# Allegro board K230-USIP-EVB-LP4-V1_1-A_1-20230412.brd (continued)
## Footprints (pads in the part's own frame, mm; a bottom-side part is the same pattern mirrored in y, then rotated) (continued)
DSW3-087044-047-H
  oval 1.778x2.54 hole 1.016x1.778: (-4.15,0) (4.15,0)
  rect 1.524x1.524 hole 1.016: 1(-2,0)
  round 1.524 hole 1.016: 2(0,0) 3(2,0)
DSW4-KH-6X6X7H-ZJ
  round 1.778 hole 1.143: 1(-2.25,-1.25) 2(2.25,-1.25)
  round 1.905 hole 1.397: 3(-3.5,1.25) 4(3.5,1.25)
F1206
  rect 1.397x1.651 smd: 1(-1.397,0) 2(1.397,0)
FB0402
  rect 0.635x0.508 smd: 1(-0.508,0) 2(0.508,0)
FB0603
  rect 0.762x0.813 smd: 1(-0.762,0) 2(0.762,0)
FB1206
  rect 1.397x1.651 smd: 1(-1.397,0) 2(1.397,0)
FPC30-005-0520-75
  rect 0.305x1.016 smd: 1(7.248,0) 2(6.748,0) 3(6.248,0) 4(5.749,0) 5(5.249,0) 6(4.749,0) 7(4.249,0) 8(3.749,0) 9(3.249,0) 10(2.749,0) 11(2.249,0) 12(1.75,0) 13(1.25,0) 14(0.75,0) 15(0.25,0) 16(-0.25,0) 17(-0.75,0) 18(-1.25,0) 19(-1.75,0) 20(-2.249,0) 21(-2.749,0) 22(-3.249,0) 23(-3.749,0) 24(-4.249,0) 25(-4.749,0) 26(-5.249,0) 27(-5.749,0) 28(-6.248,0) 29(-6.748,0) 30(-7.248,0)
  rect 2.032x1.321 smd: 31(-9.548,-2.7) 32(9.548,-2.7)
HEAD2-100
  rect 1.524x1.524 hole 1.016: 1(0,0)
  round 1.524 hole 1.016: 2(2.54,0)
HEAD2X8-100
  rect 1.524x1.524 hole 1.016: 1(0,0)
  round 1.524 hole 1.016: 2(0,2.54) 3(2.54,0) 4(2.54,2.54) 5(5.08,0) 6(5.08,2.54) 7(7.62,0) 8(7.62,2.54) 9(10.16,0) 10(10.16,2.54) 11(12.7,0) 12(12.7,2.54) 13(15.24,0) 14(15.24,2.54) 15(17.78,0) 16(17.78,2.54)
HEAD3-100
  rect 1.524x1.524 hole 1.016: 1(0,0)
  round 1.524 hole 1.016: 2(2.54,0) 3(5.08,0)
HEAD6-100
  rect 1.524x1.524 hole 1.016: 1(0,0)
  round 1.524 hole 1.016: 2(2.54,0) 3(5.08,0) 4(7.62,0) 5(10.16,0) 6(12.7,0)
HEAD10-100
  rect 1.524x1.524 hole 1.016: 1(-7.62,0)
  round 1.524 hole 1.016: 2(-5.08,0) 3(-2.54,0) 4(0,0) 5(2.54,0) 6(5.08,0) 7(7.62,0) 8(10.16,0) 9(12.7,0) 10(15.24,0)
HOLE-M3
  round 5.969 hole 3.175: 1(0,0)
LED0603
  rect 0.762x0.813 smd: 1(-0.762,0) 2(0.762,0)
MIC4-028019-010
  rect 0.635x0.635 smd: 1(0.508,0.965) 2(0.508,-0.965) 3(-0.508,-0.965) 4(-0.508,0.965)
PL02_502-01
  rect 0.762x2.413 smd: 1(-1.016,0) 2(1.016,0)
PL0303-017A
  rect 1.397x2.413 smd: 1(-1.397,0) 2(1.397,0)
PL0505-030
  rect 1.524x2.032 smd: 1(-2.112,0) 2(2.112,0)
QFN8-050-0202-008-N
  rect 0.305x0.457 smd: 1(-0.75,-0.979) 2(-0.25,-0.979) 3(0.25,-0.979) 4(0.75,-0.979) 5(0.75,0.979) 6(0.25,0.979) 7(-0.25,0.979) 8(-0.75,0.979)
  rect 1.524x0.889 smd: 9(0,0)
QFN12-040-018018-006
  rect 0.762x0.203 smd: 1(-0.9,0.2) 2(-0.9,-0.2) 7(0.9,-0.2) 8(0.9,0.2)
  rect 0.203x0.762 smd: 3(-0.6,-0.9) 4(-0.2,-0.9) 5(0.2,-0.9) 6(0.6,-0.9) 9(0.6,0.9) 10(0.2,0.9) 11(-0.2,0.9) 12(-0.6,0.9)
QFN20-050-0404-008-N
  oval 0.254x0.838 smd: 1(-1,-2.011) 2(-0.5,-2.011) 3(0,-2.011) 4(0.5,-2.011) 5(1,-2.011) 11(1,2.011) 12(0.5,2.011) 13(0,2.011) 14(-0.5,2.011) 15(-1,2.011)
  oval 0.838x0.254 smd: 6(2.011,-1) 7(2.011,-0.5) 8(2.011,0) 9(2.011,0.5) 10(2.011,1) 16(-2.011,1) 17(-2.011,0.5) 18(-2.011,0) 19(-2.011,-0.5) 20(-2.011,-1)
  rect 2.54x2.54 smd: 21(0,0)
QFN24-050-0404-010-N
  oval 0.254x0.838 smd: 1(-1.25,-2.094) 2(-0.75,-2.094) 3(-0.25,-2.094) 4(0.25,-2.094) 5(0.75,-2.094) 6(1.25,-2.094) 13(1.25,2.094) 14(0.75,2.094) 15(0.25,2.094) 16(-0.25,2.094) 17(-0.75,2.094) 18(-1.25,2.094)
  oval 0.838x0.254 smd: 7(2.094,-1.25) 8(2.094,-0.75) 9(2.094,-0.25) 10(2.094,0.25) 11(2.094,0.75) 12(2.094,1.25) 19(-2.094,1.25) 20(-2.094,0.75) 21(-2.094,0.25) 22(-2.094,-0.25) 23(-2.094,-0.75) 24(-2.094,-1.25)
  rect 2.54x2.54 smd: 25(0,0)
QFN64-050-0909-010-N
  oval 1.016x0.254 smd: 1(-4.55,3.75) 2(-4.55,3.25) 3(-4.55,2.75) 4(-4.55,2.25) 5(-4.55,1.75) 6(-4.55,1.25) 7(-4.55,0.75) 8(-4.55,0.25) 9(-4.55,-0.25) 10(-4.55,-0.75) 11(-4.55,-1.25) 12(-4.55,-1.75) 13(-4.55,-2.25) 14(-4.55,-2.75) 15(-4.55,-3.25) 16(-4.55,-3.75) 33(4.55,-3.75) 34(4.55,-3.25) 35(4.55,-2.75) 36(4.55,-2.25) 37(4.55,-1.75) 38(4.55,-1.25) 39(4.55,-0.75) 40(4.55,-0.25) 41(4.55,0.25) 42(4.55,0.75) 43(4.55,1.25) 44(4.55,1.75) 45(4.55,2.25) 46(4.55,2.75) 47(4.55,3.25) 48(4.55,3.75)
  oval 0.254x1.016 smd: 17(-3.75,-4.55) 18(-3.25,-4.55) 19(-2.75,-4.55) 20(-2.25,-4.55) 21(-1.75,-4.55) 22(-1.25,-4.55) 23(-0.75,-4.55) 24(-0.25,-4.55) 25(0.25,-4.55) 26(0.75,-4.55) 27(1.25,-4.55) 28(1.75,-4.55) 29(2.25,-4.55) 30(2.75,-4.55) 31(3.25,-4.55) 32(3.75,-4.55) 49(3.75,4.55) 50(3.25,4.55) 51(2.75,4.55) 52(2.25,4.55) 53(1.75,4.55) 54(1.25,4.55) 55(0.75,4.55) 56(0.25,4.55) 57(-0.25,4.55) 58(-0.75,4.55) 59(-1.25,4.55) 60(-1.75,4.55) 61(-2.25,4.55) 62(-2.75,4.55) 63(-3.25,4.55) 64(-3.75,4.55)
  rect 4.699x4.699 smd: 65(0,0)
R0402
  rect 0.635x0.508 smd: 1(-0.508,0) 2(0.508,0)
R0603
  rect 0.762x0.813 smd: 1(-0.762,0) 2(0.762,0)
R0805
  rect 1.016x1.397 smd: 1(-0.889,0) 2(0.889,0)
SOD523-2-28
  rect 0.508x0.406 smd: 1(-0.889,0) 2(0.889,0)
SOD523-2-28-H
  rect 0.508x0.406 smd: 1(-0.66,0) 2(0.66,0)
SOP16-75
  rect 2.032x1.016 smd: 1(-8.89,6.668) 2(-8.89,4.763) 3(-8.89,2.857) 4(-8.89,0.953) 5(-8.89,-0.953) 6(-8.89,-2.857) 7(-8.89,-4.763) 8(-8.89,-6.668) 9(8.89,-6.668) 10(8.89,-4.763) 11(8.89,-2.857) 12(8.89,-0.953) 13(8.89,0.953) 14(8.89,2.857) 15(8.89,4.763) 16(8.89,6.668)
SOT23-3-43
  rect 0.762x0.889 smd: 1(-0.95,-1.143) 2(0.95,-1.143) 3(0,1.143)
SOT23-5-36
  rect 0.635x1.016 smd: 1(-0.953,-1.295) 2(0,-1.295) 3(0.953,-1.295) 4(0.953,1.295) 5(-0.953,1.295)
SOT23-5-57
  rect 0.635x1.016 smd: 1(-0.953,-1.245) 2(0,-1.245) 3(0.953,-1.245) 4(0.953,1.245) 5(-0.953,1.245)
SOT143-4-48
  rect 1.016x1.143 smd: 1(-0.747,-1.143)
  rect 0.635x1.143 smd: 2(0.953,-1.143) 3(0.953,1.143) 4(-0.953,1.143)
SW2-061036-025
  rect 2.032x1.016 smd: 1(3.016,0) 2(-3.016,0)
SW4-100-060050-035
  rect 1.016x2.159 smd: 1(-1.27,-4.386) 2(1.27,-4.386) 3(-1.27,4.386) 4(1.27,4.386)
TC1206
  rect 1.397x1.651 smd: 1(-1.397,0) 2(1.397,0)
TP28
  round 0.711 smd: 1(0,0)
TP40
  round 1.016 smd: 1(0,0)
TYPE-C-USB16-20-126-H-SMD-B
  round 0.711 hole 0.711 unplated: (-2.89,2.6) (2.89,2.6)
  rect 0.305x1.448 smd: A1(-3.375,3.974) A4(-2.6,3.974) A5(-1.25,3.974) A6(-0.25,3.974) A7(0.25,3.974) A8(1.25,3.974) A9(2.6,3.974) A12(3.375,3.974) B1(3.075,3.974) B4(2.3,3.974) B5(1.75,3.974) B6(0.75,3.974) B7(-0.75,3.974) B8(-1.75,3.974) B9(-2.3,3.974) B12(-3.075,3.974)
  oval 1.143x2.159 hole 0.762x1.778: P1(-4.32,3.13) P2(4.32,3.13)
  oval 1.143x1.651 hole 0.762x1.27: P3(-4.32,-1.05) P4(4.32,-1.05)
unnamed
  round 1.016 smd: 1(0,0)
X2-3215-008
  rect 1.016x1.778 smd: 1(-1.257,0) 2(1.257,0)
X4-2520-010
  rect 1.016x0.889 smd: 1(-0.914,-0.762) 2(0.914,-0.762) 3(0.914,0.762) 4(-0.914,0.762)
X4-3225-007
  rect 1.27x1.143 smd: 1(-1.1,-0.8) 2(1.1,-0.8) 3(1.1,0.8) 4(-1.1,0.8)

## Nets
AVDD_1V8: C14.1 C15.1 C151.1 C361.1 C362.1 FB27.2 R35.1 R80.1 R131.2 R132.1 TP11.1(TP) U1.F7(AVDD1P8_CODEC) U1.F8(AVDD1P8_ADC)
AVDD_PLL_0V8: C32.1 C365.1 C366.1 FB29.2 TP7.1(TP) U1.G11(AVDD0P8_PLL)
GND: C1.2 C2.2 C3.2 C4.2 C5.2 C6.2 C7.2 C8.2 C9.2 C10.2 C11.2 C12.2 C13.1 C14.2 C15.2 C16.1 C17.2 C18.2 C19.2 C20.1 C21.2 C22.2 C23.1 C24.2 C25.2 C26.2 C27.2 C28.2 C29.2 C30.2 C31.2 C32.2 C33.2 C34.2 C35.2 C36.2 C37.2 C38.2 C39.2 C40.2 C41.2 C42.2 C43.2 C44.2 C45.2 C46.2 C47.2 C48.2 C49.2 C50.2 C51.2 C52.2 C53.2 C54.2 C55.2 C56.2 C57.2 C58.2 C59.2 C60.2 C61.2 C63.2 C64.2 C65.2 C66.2 C67.2 C68.2 C69.2 C70.2 C71.2 C72.2 C73.2 C74.2 C75.2 C76.2 C77.2 C78.2 C79.2 C80.2 C81.2 C82.2 C83.2 C84.2 C85.2 C86.2 C87.2 C88.2 C89.2 C90.2 C91.2 C92.2 C93.2 C94.2 C95.2 C96.2 C97.2 C98.2 C99.2 C100.2 C101.2 C102.2 C103.2 C104.2 C105.2 C106.2 C107.2 C108.2 C109.2 C110.2 C111.2 C112.2 C113.2 C114.2 C115.2 C116.2 C117.2 C118.2 C119.2 C120.2 C121.2 C122.2 C123.2 C127.2 C128.1 C129.2 C139.2 C145.2 C149.2 C150.2 C151.2 C152.2 C153.2 C154.2 C155.2 C156.2 C158.1 C160.1 C162.2 C199.1 C200.1 C201.2 C202.1 C203.1 C204.2 C205.2 C206.1 C207.2 C208.1 C216.1 C217.1 C218.1 C219.1 C220.1 C221.1 C222.1 C223.2 C224.2 C225.2 C226.2 C227.1 C242.1 C244.1 C247.2 C248.2 C249.2 C250.2 C251.2 C252.2 C253.2 C254.2 C256.2 C257.2 C258.2 C259.2 C260.2 C261.1 C262.2 C263.2 C264.2 C265.2 C266.2 C268.2 C269.2 C272.2 C273.2 C274.2 C275.2 C276.2 C277.2 C278.2 C279.2 C280.2 C281.2 C282.2 C283.2 C284.2 C285.2 C286.2 C287.2 C288.2 C289.2 C290.2 C291.2 C292.2 C293.2 C294.2 C295.2 C296.2 C297.2 C298.2 C299.2 C300.2 C301.2 C302.2 C303.2 C304.2 C305.2 C306.2 C307.2 C308.2 C310.1 C312.1 C313.2 C314.2 C315.2 C316.1 C317.2 C318.2 C319.2 C321.2 C322.2 C324.2 C325.2 C326.2 C327.2 C329.2 C330.2 C331.2 C333.2 C334.2 C335.2 C336.2 C337.2 C338.2 C339.2 C340.2 C341.2 C342.2 C343.2 C344.2 C345.2 C346.2 C347.2 C348.2 C349.2 C350.2 C351.2 C352.2 C353.2 C354.2 C357.2 C358.2 C359.2 C360.2 C361.2 C362.2 C365.2 C366.2 C367.1 C368.2 C369.1 C370.2 C371.2 C372.2 C373.2 C374.2 C375.2 C376.2 C377.1 C378.2 C379.2 C380.2 C381.1 C383.2 C394.2 C395.2 C396.2 C397.2 C398.2 C399.2 C400.2 C401.2 C402.2 C403.1 C404.1 D1.1(ANODE) J1.6 J1.12 J2.A1(GND0) J2.A12(GND1) J2.B1(GND3) J2.B12(GND2) J2.P1 J2.P2 J2.P3 J2.P4 J3.5 J3.6 J3.11 J3.12 J3.17 J3.18 J3.23 J3.24 J3.28 J3.29 J3.33 J3.37 J3.54 J3.55 J4.1 J4.2 J4.7 J4.12 J4.15 J4.18 J4.21 J4.24 J4.27 J4.30 J4.31 J4.32 J5.5 J5.11 J5.12 J6.A1(GND0) J6.A12(GND1) J6.B1(GND3) J6.B12(GND2) J6.P1 J6.P2 J6.P3 J6.P4 J7.2 J8.10 J8.14 J9.2 J9.15 J11.A1(GND0) J11.A12(GND1) J11.B1(GND3) J11.B12(GND2) J11.P1 J11.P2 J11.P3 J11.P4 J12.2 J12.9 J12.10 J13.A1(GND0) J13.A12(GND1) J13.B1(GND3) J13.B12(GND2) J13.P1 J13.P2 J13.P3 J13.P4 J14.1 J14.2 J17.2 K1.3 K1.4 K2.1 K4.3 LED1.2(ANODE) M1.1 M2.1 M3.1 M4.1 M5.1 M6.1 Q2.2(SOURCE) R7.2 R9.2 R13.2 R14.2 R40.1 R41.2 R42.2 R44.2 R45.1 R46.2 R56.1 R58.2 R61.2 R72.2 R73.2 R74.2 R130.1 R133.2 R134.2 R137.1 R178.2 R195.2 R202.1 R252.1 R266.1 R268.1 R271.2 R276.1 R278.1 R279.2 R282.1 R286.2 R290.2 R296.2 TP15.1(TP) TP16.1(TP) TP17.1(TP) TP18.1(TP) TP19.1(TP) TP20.1(TP) TP21.1(TP) TP22.1(TP) TVS1.2(A2) TVS2.2(A2) TVS3.2(A2) TVS4.2(A2) TVS5.2(A2) TVS6.2(A2) TVS7.2(A2) TVS8.2(A2) TVS9.2(A2) TVS10.2(A2) TVS11.2(A2) TVS12.2(A2) TVS13.2(A2) TVS14.2(A2) U1.A13(VSS91) U1.A16(VSS90) U1.A19(VSS92) U1.B13(VSS93) U1.B20(VSS94) U1.C13(VSS95) U1.D9(VSS96) U1.D10(VSS99) U1.D11(VSS97) U1.D13(VSS98) U1.D15(VSS100) U1.E4(VSS75) U1.E6(VSS72) U1.E7(VSS73) U1.E8(VSS74) U1.E12(VSS78) U1.E13(VSS79) U1.E14(VSS80) U1.E15(VSS81) U1.E16(VSS82) U1.E19(VSS77) U1.F4(VSS53) U1.F6(VSS55) U1.F10(VSS76) U1.F11(AVSS3) U1.F16(VSS54) U1.G6(VSS89) U1.G7(AVSS2) U1.G8(AVSS1) U1.G13(VSS49) U1.G14(VSS50) U1.G15(VSS51) U1.G16(VSS52) U1.H7(VSS88) U1.H11(VSS83) U1.H13(VSS85) U1.H15(VSS86) U1.H16(VSS87) U1.H20(VSS84) U1.J7(VSS3) U1.J11(VSS1) U1.J13(VSS0) U1.J15(VSS2) U1.K3(VSS4) U1.K6(VSS7) U1.K8(VSS9) U1.K10(VSS10) U1.K12(VSS8) U1.K14(VSS6) U1.K16(VSS5) U1.K18(VSS56) U1.L7(VSS11) U1.L8(VSS12) U1.L10(VSS14) U1.L12(VSS16) U1.L15(VSS15) U1.L19(VSS13) U1.M6(VSS17) U1.M8(VSS19) U1.M10(VSS20) U1.M12(VSS18) U1.M15(VSS21) U1.M16(VSS22) U1.N3(VSS26) U1.N5(VSS24) U1.N8(VSS27) U1.N10(VSS23) U1.N12(VSS25) U1.N15(VSS28) U1.N16(VSS29) U1.P6(VSS30) U1.P7(VSS31) U1.P8(VSS32) U1.P10(VSS34) U1.P12(VSS33) U1.P14(VSS43) U1.P15(VSS44) U1.P20(VSS40) U1.R3(VSS36) U1.R6(VSS38) U1.R7(VSS39) U1.R10(VSS41) U1.R12(VSS42) U1.R14(VSS35) U1.R16(VSS37) U1.T3(VSS48) U1.T7(VSS45) U1.T8(VSS46) U1.T9(VSS47) U1.T15(VSS60) U1.U3(VSS59) U1.U8(VSS58) U1.U19(VSS57) U1.V3(VSS61) U1.V4(VSS62) U1.V5(VSS63) U1.V6(VSS64) U1.V7(VSS65) U1.V8(VSS66) U1.W1(VSS67) U1.W16(VSS68) U1.W20(VSS71) U1.Y13(VSS69) U1.Y19(VSS70) U3.2(GND) U4.6(VSS) U4.10(GND1) U4.11(GND2) U4.12(GND3) U4.13(GND4) U5.A3(VSS1) U5.A10(VSS2) U5.AB3(VSS55) U5.AB5(VSS56) U5.AB8(VSS57) U5.AB10(VSS58) U5.C1(VSS3) U5.C5(VSS4) U5.C8(VSS5) U5.C12(VSS6) U5.D2(VSS7) U5.D4(VSS8) U5.D9(VSS9) U5.D11(VSS10) U5.E1(VSS11) U5.E5(VSS12) U5.E8(VSS13) U5.E12(VSS14) U5.G1(VSS15) U5.G3(VSS16) U5.G5(VSS17) U5.G8(VSS18) U5.G10(VSS19) U5.G12(VSS20) U5.J1(VSS21) U5.J3(VSS22) U5.J10(VSS23) U5.J12(VSS24) U5.K2(VSS25) U5.K4(VSS26) U5.K9(VSS27) U5.K11(VSS28) U5.N2(VSS29) U5.N4(VSS30) U5.N9(VSS31) U5.N11(VSS32) U5.P1(VSS33) U5.P3(VSS34) U5.P10(VSS35) U5.P12(VSS36) U5.T1(VSS37) U5.T3(VSS38) U5.T5(VSS39) U5.T8(VSS40) U5.T10(VSS41) U5.T12(VSS42) U5.V1(VSS43) U5.V5(VSS44) U5.V8(VSS45) U5.V12(VSS46) U5.W2(VSS47) U5.W4(VSS48) U5.W9(VSS49) U5.W11(VSS50) U5.Y1(VSS51) U5.Y5(VSS52) U5.Y8(VSS53) U5.Y12(VSS54) U6.2(GND) U7.A3(VSS1) U7.A10(VSS2) U7.AB3(VSS55) U7.AB5(VSS56) U7.AB8(VSS57) U7.AB10(VSS58) U7.C1(VSS3) U7.C5(VSS4) U7.C8(VSS5) U7.C12(VSS6) U7.D2(VSS7) U7.D4(VSS8) U7.D9(VSS9) U7.D11(VSS10) U7.E1(VSS11) U7.E5(VSS12) U7.E8(VSS13) U7.E12(VSS14) U7.G1(VSS15) U7.G3(VSS16) U7.G5(VSS17) U7.G8(VSS18) U7.G10(VSS19) U7.G12(VSS20) U7.J1(VSS21) U7.J3(VSS22) U7.J10(VSS23) U7.J12(VSS24) U7.K2(VSS25) U7.K4(VSS26) U7.K9(VSS27) U7.K11(VSS28) U7.N2(VSS29) U7.N4(VSS30) U7.N9(VSS31) U7.N11(VSS32) U7.P1(VSS33) U7.P3(VSS34) U7.P10(VSS35) U7.P12(VSS36) U7.T1(VSS37) U7.T3(VSS38) U7.T5(VSS39) U7.T8(VSS40) U7.T10(VSS41) U7.T12(VSS42) U7.V1(VSS43) U7.V5(VSS44) U7.V8(VSS45) U7.V12(VSS46) U7.W2(VSS47) U7.W4(VSS48) U7.W9(VSS49) U7.W11(VSS50) U7.Y1(VSS51) U7.Y5(VSS52) U7.Y8(VSS53) U7.Y12(VSS54) U9.3(GND) U9.7(POWERPAD) U16.4(PGND1) U16.12(PGND2) U16.18(AGND) U16.21(EXP) U22.1(GND) U23.1(GND) U24.1(GND) U25.7(GND) U26.1(GND#1) U26.5(GND#5) U26.10(AGND) U26.11(GND#11) U26.13(TEST) U26.15(GND#15) U26.25(GND#25) U26.35(GND#35) U26.47(GND#47) U26.51(GND#51) U26.65(PAD) U29.2(GND1) U29.3(GND2) U30.A6(VSS#A6) U30.C4(VSSQ#C4) U30.E7(VSS#E7) U30.G5(VSS#G5) U30.H10(VSS#H10) U30.J5(VSS#J5) U30.K8(VSS#K8) U30.N2(VSSQ#N2) U30.N5(VSSQ#N5) U30.P4(VSSQ#P4) U30.P6(VSSQ#P6) U31.1(GND) U32.1(GND) U33.1(GND) U34.7(GND) U35.4(GND2) U35.25(GND4) U36.7(GND) U37.3(GND) U37.7(POWERPAD) U38.4(PGND1) U38.8(SGND) U38.9(PGND2) Y3.2(GND#2) Y3.4(GND#4) Y5.2(GND#2) Y5.4(GND#4)
GND3: R289.1 R290.1 U35.1(GND3)
VBUS: F1.1 J2.A4(VBUS0) J2.A9(VBUS1) J2.B4(VBUS3) J2.B9(VBUS2)
VBUS_IN: C9.1 C12.1 C247.1 C248.1 C249.1 C250.1 D1.2(CATHODE) F1.2 Q5.2(SOURCE) R303.1
VDD0V8_KPU_EN: C394.1 R301.1 U38.7(EN)
VDD_0V8: C317.1 C318.1 C319.1 C320.1 FB29.1 FB31.1 FB32.1 L5.2 R267.2 R309.1 R310.1
VDD_1V1: C325.1 C326.1 C327.1 C328.1 L7.2 R275.1 R307.1
VDD_1V8: C23.2 C26.1 C28.1 C29.1 C31.1 C78.1 C79.1 C80.1 C206.2 C207.1 C242.2 C256.1 C257.1 C258.1 C259.1 C315.1 C321.1 C322.1 C323.1 C324.1 FB5.2 FB19.1 FB26.1 FB27.1 J5.7 J5.9 J8.12 J9.1 J12.1 L11.2 R18.2 R20.2 R48.2 R49.2 R59.2 R129.1 R146.1 R197.1 R198.1 R199.1 R200.1 R206.1 R207.1 R209.1 R234.1 R235.1 R236.1 R237.1 R238.1 R239.1 R240.1 R241.1 R269.2 R280.2 R311.1 R312.1 TP9.1(TP) U1.E11(VDD1P8#E11) U1.F13(VDD1P8#F13) U1.H6(VDDIO3P3_3) U1.R11(VDDIO3P3_2) U1.R13(VDDIO3P3_0) U1.R15(VDDIO3P3_5) U25.2(VCCA) U30.C6(VCCQ#C6) U30.M4(VCCQ#M4) U30.N4(VCCQ#N4) U30.P3(VCCQ#P3) U30.P5(VCCQ#P5) U34.2(VCCA)
VDD_3V3: C18.1 C19.1 C22.1 C30.1 C81.1 C82.1 C83.1 C139.1 C145.1 C208.2 C227.2 C244.2 C260.1 C316.2 C367.2 C399.1 C403.2 FB4.2 J3.57 J3.59 J4.5 J4.6 J5.13 J5.15 J8.16 J9.16 R11.2 R19.1 R76.1 R162.1 R188.1 R189.1 R190.1 R191.1 R193.1 R194.1 R242.1 R243.1 R245.2 R283.2 R284.2 R288.1 R305.2 R306.2 R308.2 TP10.1(TP) U1.E10(VDD3P3_SD) U1.M7(VDDIO3P3_4) U4.4(VDD) U25.1(VCCB) U30.E6(VCC#E6) U30.F5(VCC#F5) U30.J10(VCC#J10) U30.K9(VCC#K9) U34.1(VCCB) U36.2(VCCA)
VDD_5V: C2.1 C127.1 C337.1 C338.1 C339.1 C340.1 C379.1 C381.2 C383.1 C397.1 C398.1 C401.1 Q1.2(SOURCE) Q5.3(DRAIN) R23.2 R75.1 R143.1 R265.2 R272.2 R273.2 R274.2 R277.1 R289.2 R293.1 R301.2 R302.1 R304.1 TP23.1(TP) U9.6(IN) U35.8(VIN2) U35.11(VIN1) U35.20(VIN4) U35.23(VIN3) U38.3(IN) U39.1(VIN) U39.2(GND)
VDD_5V_O: C16.2 C20.2 J3.56 J3.58 J3.60 J4.3 J4.4 J5.14 J5.16 Q1.3(DRAIN) R39.2 R43.2 R75.2 R88.2 TP24.1(TP) U3.5(IN) U6.5(IN)
VDD_CORE_0V8: C33.1 C34.1 C35.1 C36.1 C37.1 C38.1 C39.1 C40.1 C41.1 C42.1 C43.1 C44.1 C45.1 C46.1 C47.1 C48.1 C57.1 C58.1 C59.1 C60.1 C61.1 C251.1 C253.1 C351.1 C352.1 C371.1 C372.1 FB31.2 TP5.1(TP) TP6.1(TP) U1.F12(VDD0P8_CORE#F12) U1.G9(VDD0P8_CORE#G9) U1.G10(VDD0P8_CORE#G10) U1.G12(VDD0P8_CPU#G12) U1.H12(VDD0P8_CPU#H12) U1.J12(VDD0P8_CPU#J12) U1.K9(VDD0P8_CORE#K9) U1.K11(VDD0P8_CORE#K11) U1.L9(VDD0P8_CORE#L9) U1.L11(VDD0P8_CORE#L11) U1.M9(VDD0P8_CORE#M9) U1.M11(VDD0P8_CORE#M11) U1.N9(VDD0P8_CORE#N9) U1.N11(VDD0P8_CORE#N11) U1.P9(VDD0P8_CORE#P9) U1.P11(VDD0P8_CORE#P11) U1.P13(VDD0P8_CORE#P13)
VDD_KPU_0V8: C49.1 C50.1 C51.1 C52.1 C53.1 C54.1 C55.1 C56.1 C252.1 C254.1 C353.1 C354.1 C373.1 C374.1 C375.1 C376.1 C400.1 FB32.2 FB34.2 FB38.2 TP8.1(TP) U1.H8(VDD0P8_KPU#H8) U1.H9(VDD0P8_KPU#H9) U1.H10(VDD0P8_KPU#H10) U1.J8(VDD0P8_KPU#J8) U1.J9(VDD0P8_KPU#J9) U1.J10(VDD0P8_KPU#J10)
VDD_PA: C7.1 C303.1 C304.1 C308.1 R11.1 R88.1 U16.3(PVDD1) U16.9(AVDD) U16.13(PVDD2)
3D_CTRL_IN: J3.49 R83.1
3D_CTRL_OUT1: J3.47 R85.1
3D_CTRL_OUT2: J3.46 R87.1
ACRC: C313.1 R134.1 U16.1(ACRC)
ADC_0: J15.1 R25.1 R51.1
ADC_1: J15.2 R26.1 R52.1
ADC_2: J3.52 J15.3 R27.1
ADC_3: J15.4 R28.1
ADC_4: J15.5 R29.1
ADC_5: J15.6 R30.1 R221.1
BOOT0: R18.1 SW1.1(A1) TVS4.1(A1) U1.C8(GPIO0)
BOOT1: R20.1 SW1.2(A2) TVS5.1(A1) U1.C9(GPIO1)
CA_A0: U1.M19(DDR_A5_CA4_CAA0) U5.H2(CA0_A)
CA_A1: U1.L16(DDR_A6_CA5_CAA1) U5.J2(CA1_A)
CA_A2: U1.N19(DDR_A8_CA6_CAA2) U5.H9(CA2_A)
CA_A3: U1.N20(DDR_A7_CA7_CAA3) U5.H10(CA3_A)
CA_A4: U1.M18(DDR_A11_CA8_CAA4) U5.H11(CA4_A)
CA_A5: U1.P19(DDR_A12_CA9_CAA5) U5.J11(CA5_A)
CA_B0: U1.E20(DDR_A13_NA_CAB0) U7.H2(CA0_A)
CA_B1: U1.G19(DDR_BA0_NA_CAB1) U7.J2(CA1_A)
CA_B2: U1.G18(DDR_A10_NA_CAB2) U7.H9(CA2_A)
CA_B3: U1.H17(DDR_A0_NA_CAB3) U7.H10(CA3_A)
CA_B4: U1.F17(DDR_NA_NA_CAB4) U7.H11(CA4_A)
CA_B5: U1.F19(DDR_CASN_NA_CAB5) U7.J11(CA5_A)
CC1: J2.A5(CC1) J2.B5(CC2) R9.1
CC_T: J6.A5(CC1) J6.B5(CC2) R195.1
CK_C_A: U1.R20(DDR_A14_CLKN_CLKAN) U5.J9(CK_C_A)
CK_C_B: U1.F20(DDR_A1_NA_CLKBN) U7.J9(CK_C_A)
CK_T_A: U1.R19(DDR_BA2_CLK_CLKA) U5.J8(CK_T_A)
CK_T_B: U1.G20(DDR_A2_NA_CLKB) U7.J8(CK_T_A)
CKE_A: U1.N17(DDR_CKE0_CKE0_CKEA0) U5.J4(CKE0_A)
CKE_B: U1.J18(DDR_CLK1_NA_CKEB0) U7.J4(CKE0_A)
CS_A: U1.T20(DDR_CS0N_CS0_CSA0) U5.H4(CS0_A)
CS_B: U1.J20(DDR_NA_NA_CSB0) U7.H4(CS0_A)
DDR_1V8: C115.1 C116.1 C117.1 C118.1 C119.1 C120.1 C121.1 C296.1 C297.1 C298.1 C299.1 C300.1 C301.1 C302.1 C341.1 C342.1 R312.2 TP1.1(TP) U5.F1(VDD1#F1) U5.F12(VDD1#F12) U5.G4(VDD1#G4) U5.G9(VDD1#G9) U5.T4(VDD1#T4) U5.T9(VDD1#T9) U5.U1(VDD1#U1) U5.U12(VDD1#U12) U7.F1(VDD1#F1) U7.F12(VDD1#F12) U7.G4(VDD1#G4) U7.G9(VDD1#G9) U7.T4(VDD1#T4) U7.T9(VDD1#T9) U7.U1(VDD1#U1) U7.U12(VDD1#U12)
DDR_CORE_0V8: C63.1 C64.1 C65.1 C66.1 C67.1 C68.1 C395.1 C396.1 R309.2 TP3.1(TP) U1.K13(VDD0P8_DDR_CORE#K13) U1.L13(VDD0P8_DDR_CORE#L13) U1.M13(VDD0P8_DDR_CORE#M13) U1.N13(VDD0P8_DDR_CORE#N13)
DDR_VAA_1V8: C76.1 C77.1 C269.1 C359.1 C360.1 FB26.2 TP2.1(TP) U1.K15(VAA_DDR)
DDR_VDDQ_1V1: C62.2 C69.1 C70.1 C71.1 C72.1 C73.1 C74.1 C75.1 C91.1 C92.1 C93.1 C94.1 C95.1 C96.1 C97.1 C98.1 C99.1 C100.1 C101.1 C102.1 C103.1 C104.1 C105.1 C106.1 C107.1 C108.1 C109.1 C110.1 C111.1 C112.1 C113.1 C114.1 C122.1 C123.1 C263.1 C264.1 C265.1 C266.1 C272.1 C273.1 C274.1 C275.1 C276.1 C277.1 C278.1 C279.1 C280.1 C281.1 C282.1 C283.1 C284.1 C285.1 C286.1 C287.1 C288.1 C289.1 C290.1 C291.1 C292.1 C293.1 C294.1 C295.1 C347.1 C348.1 R57.1 R63.2 R66.2 R67.2 R69.2 R307.2 TP4.1(TP) U1.H14(VDD1P1_DDR_IO#H14) U1.J14(VDD1P1_DDR_IO#J14) U1.L14(VDD1P1_DDR_IO#L14) U1.M14(VDD1P1_DDR_IO#M14) U1.N14(VDD1P1_DDR_IO#N14) U5.A4(VDD2#A4) U5.A9(VDD2#A9) U5.AA3(VDDQ#AA3) U5.AA5(VDDQ#AA5) U5.AA8(VDDQ#AA8) U5.AA10(VDDQ#AA10) U5.AB4(VDD2#AB4) U5.AB9(VDD2#AB9) U5.B3(VDDQ#B3) U5.B5(VDDQ#B5) U5.B8(VDDQ#B8) U5.B10(VDDQ#B10) U5.D1(VDDQ#D1) U5.D5(VDDQ#D5) U5.D8(VDDQ#D8) U5.D12(VDDQ#D12) U5.F3(VDDQ#F3) U5.F5(VDD2#F5) U5.F8(VDD2#F8) U5.F10(VDDQ#F10) U5.H1(VDD2#H1) U5.H5(VDD2#H5) U5.H8(VDD2#H8) U5.H12(VDD2#H12) U5.K1(VDD2#K1) U5.K3(VDD2#K3) U5.K10(VDD2#K10) U5.K12(VDD2#K12) U5.N1(VDD2#N1) U5.N3(VDD2#N3) U5.N10(VDD2#N10) U5.N12(VDD2#N12) U5.R1(VDD2#R1) U5.R5(VDD2#R5) U5.R8(VDD2#R8) U5.R12(VDD2#R12) U5.U3(VDDQ#U3) U5.U5(VDD2#U5) U5.U8(VDD2#U8) U5.U10(VDDQ#U10) U5.W1(VDDQ#W1) U5.W5(VDDQ#W5) U5.W8(VDDQ#W8) U5.W12(VDDQ#W12) U7.A4(VDD2#A4) U7.A9(VDD2#A9) U7.AA3(VDDQ#AA3) U7.AA5(VDDQ#AA5) U7.AA8(VDDQ#AA8) U7.AA10(VDDQ#AA10) U7.AB4(VDD2#AB4) U7.AB9(VDD2#AB9) U7.B3(VDDQ#B3) U7.B5(VDDQ#B5) U7.B8(VDDQ#B8) U7.B10(VDDQ#B10) U7.D1(VDDQ#D1) U7.D5(VDDQ#D5) U7.D8(VDDQ#D8) U7.D12(VDDQ#D12) U7.F3(VDDQ#F3) U7.F5(VDD2#F5) U7.F8(VDD2#F8) U7.F10(VDDQ#F10) U7.H1(VDD2#H1) U7.H5(VDD2#H5) U7.H8(VDD2#H8) U7.H12(VDD2#H12) U7.K1(VDD2#K1) U7.K3(VDD2#K3) U7.K10(VDD2#K10) U7.K12(VDD2#K12) U7.N1(VDD2#N1) U7.N3(VDD2#N3) U7.N10(VDD2#N10) U7.N12(VDD2#N12) U7.R1(VDD2#R1) U7.R5(VDD2#R5) U7.R8(VDD2#R8) U7.R12(VDD2#R12) U7.U3(VDDQ#U3) U7.U5(VDD2#U5) U7.U8(VDD2#U8) U7.U10(VDDQ#U10) U7.W1(VDDQ#W1) U7.W5(VDDQ#W5) U7.W8(VDDQ#W8) U7.W12(VDDQ#W12)
DDR_VREF: C62.1 C261.2 C262.1 R57.2 R58.1 U1.K17(DDR_VREF)
DEBUG_DM: J6.A7(DN1) J6.B7(DN2) U26.7(DM)
DEBUG_DP: J6.A6(DP1) J6.B6(DP2) U26.8(DP)
DL_M_CLK2: J3.31 J17.1 R116.2
DL_M_CLK3: J3.35 R118.2
DMI0_A: U1.V17(DDR_DM0_DM3_DMIA0) U5.C3(DMI0_A)
DMI0_B: U1.D18(DDR_DM2_DM0_DMIB1) U7.C3(DMI0_A)
DMI1_A: U1.P17(DDR_DM1_DM1_DMIA1) U5.C10(DMI1_A)
DMI1_B: U1.C15(DDR_DM3_DM2_DMIB0) U7.C10(DMI1_A)
DP_M_CLK1: J3.26 R89.1
DP_RST: J3.44 R179.1
DP_STROBE: J3.50 R181.1
DP_VSYNC: J3.48 R180.1
DQ_A0: U1.U16(DDR_DQ7_DQ31_DQA0) U5.B2(DQ0_A)
DQ_A1: U1.T16(DDR_DQ6_DQ30_DQA1) U5.C2(DQ1_A)
DQ_A2: U1.V16(DDR_DQ5_DQ29_DQA2) U5.E2(DQ2_A)
DQ_A3: U1.Y16(DDR_DQ4_DQ28_DQA3) U5.F2(DQ3_A)
DQ_A4: U1.W18(DDR_DQ3_DQ27_DQA4) U5.F4(DQ4_A)
DQ_A5: U1.V18(DDR_DQ2_DQ26_DQA5) U5.E4(DQ5_A)
DQ_A6: U1.Y18(DDR_DQ1_DQ25_DQA6) U5.C4(DQ6_A)
DQ_A7: U1.U17(DDR_DQ0_DQ24_DQA7) U5.B4(DQ7_A)
DQ_A8: U1.R17(DDR_DQ8_DQ8_DQA8) U5.B11(DQ8_A)
DQ_A9: U1.T18(DDR_DQ9_DQ9_DQA9) U5.C11(DQ9_A)
DQ_A10: U1.R18(DDR_DQ10_DQ10_DQA10) U5.E11(DQ10_A)
DQ_A11: U1.U20(DDR_DQ11_DQ11_DQA11) U5.F11(DQ11_A)
DQ_A12: U1.W19(DDR_DQ12_DQ12_DQA12) U5.F9(DQ12_A)
DQ_A13: U1.U18(DDR_DQ13_DQ13_DQA13) U5.E9(DQ13_A)
DQ_A14: U1.P16(DDR_DQ14_DQ14_DQA14) U5.C9(DQ14_A)
DQ_A15: U1.T17(DDR_DQ15_DQ15_DQA15) U5.B9(DQ15_A)
DQ_B0: U1.D17(DDR_DQ18_DQ2_DQB13) U7.B2(DQ0_A)
DQ_B1: U1.D16(DDR_DQ17_DQ1_DQB14) U7.C2(DQ1_A)
DQ_B2: U1.E18(DDR_DQ20_DQ4_DQB11) U7.E2(DQ2_A)
DQ_B3: U1.E17(DDR_DQ21_DQ5_DQB10) U7.F2(DQ3_A)
DQ_B4: U1.C17(DDR_DQ16_DQ0_DQB15) U7.F4(DQ4_A)
DQ_B5: U1.C18(DDR_DQ19_DQ3_DQB12) U7.E4(DQ5_A)
DQ_B6: U1.C19(DDR_DQ23_DQ7_DQB8) U7.C4(DQ6_A)
DQ_B7: U1.B19(DDR_DQ22_DQ6_DQB9) U7.B4(DQ7_A)
DQ_B8: U1.D14(DDR_DQ25_DQ17_DQB1) U7.B11(DQ8_A)
DQ_B9: U1.A14(DDR_DQ27_DQ19_DQB3) U7.C11(DQ9_A)
DQ_B10: U1.B14(DDR_DQ26_DQ18_DQB2) U7.E11(DQ10_A)
DQ_B11: U1.C14(DDR_DQ24_DQ16_DQB0) U7.F11(DQ11_A)
DQ_B12: U1.B17(DDR_DQ31_DQ23_DQB7) U7.F9(DQ12_A)
DQ_B13: U1.C16(DDR_DQ30_DQ22_DQB6) U7.E9(DQ13_A)
DQ_B14: U1.A17(DDR_DQ28_DQ20_DQB4) U7.C9(DQ14_A)
DQ_B15: U1.B16(DDR_DQ29_DQ21_DQB5) U7.B9(DQ15_A)
DQS0_C_A: U1.Y17(DDR_DQS0N_DQS3N_DQSA0N) U5.E3(DQS0_C_A)
DQS0_C_B: U1.A18(DDR_DQS2N_DQS0N_DQSB1N) U7.E3(DQS0_C_A)
DQS0_T_A: U1.W17(DDR_DQS0_DQS3_DQSA0) U5.D3(DQS0_T_A)
DQS0_T_B: U1.B18(DDR_DQS2_DQS0_DQSB1) U7.D3(DQS0_T_A)
DQS1_C_A: U1.V19(DDR_DQS1N_DQS1N_DQSA1N) U5.E10(DQS1_C_A)
DQS1_C_B: U1.A15(DDR_DQS3N_DQS2N_DQSB0N) U7.E10(DQS1_C_A)
DQS1_T_A: U1.V20(DDR_DQS1_DQS1_DQSA1) U5.D10(DQS1_T_A)
DQS1_T_B: U1.B15(DDR_DQS3_DQS2_DQSB0) U7.D10(DQS1_T_A)
EMMC_CLK: R50.1 U1.A5(MMC0_CLK)
EMMC_CMD: R48.1 U1.D6(MMC0_CMD) U30.M5(CMD)
EMMC_D0: U1.D5(MMC0_D0) U30.A3(DAT0)
EMMC_D1: U1.C5(MMC0_D1) U30.A4(DAT1)
EMMC_D2: U1.B5(MMC0_D2) U30.A5(DAT2)
EMMC_D3: U1.C6(MMC0_D3) U30.B2(DAT3)
EMMC_D4: U1.D7(MMC0_D4) U30.B3(DAT4)
EMMC_D5: U1.A7(MMC0_D5) U30.B4(DAT5)
EMMC_D6: U1.B7(MMC0_D6) U30.B5(DAT6)
EMMC_D7: U1.C7(MMC0_D7) U30.B6(DAT7)
EMMC_RST: C25.1 R49.1 U1.A6(MMC0_RST_N) U30.K5(R\E\S\E\T\)
EMMC_STROBE: R47.1 R59.1 U1.B6(MMC0_STROBE)
FT_12MHZ_IN: C201.1 U26.2(OSCI) Y5.3(IN)
FT_12MHZ_OUT: C204.1 U26.3(OSCO) Y5.1(OUT)
FTVCC_1V8: C199.2 C202.2 C220.2 C221.2 C222.2 U26.12(VCORE#12) U26.37(VCORE#37) U26.49(VREGOUT) U26.64(VCORE#64)
FTVCC_3V3: C200.2 C203.2 C216.2 C217.2 C218.2 C219.2 C368.1 FB7.1 FB8.1 R201.1 R203.1 R204.1 R205.1 R287.2 R288.2 U26.20(VCCIO#20) U26.31(VCCIO#31) U26.42(VCCIO#42) U26.50(VREGIN) U26.56(VCCIO#56) U36.1(VCCB)
G0: R131.1 R133.1 TP28.1(TP) U16.15(G0)
GPIO9: R81.1 R184.2
GPIO26: J8.1 R91.1
GPIO27: J3.36 J8.2 R93.1
GPIO28: J3.42 J8.3 R95.1
GPIO29: J8.4 R97.1 R182.2
GPIO30: J8.5 R99.1 R183.2
GPIO31: J8.8 R101.1 R208.2
GPIO32: J8.6 R103.1
GPIO33: J8.7 R105.1
GPIO34: J8.9 R107.1
GPIO35: J8.11 R109.1
GPIO36: J8.13 R111.1
GPIO37: J8.15 R113.1
GPIO42: R100.2 R181.2
GPIO43: R102.2 R180.2
GPIO46: R108.2 R179.2
GPIO47: J3.30 R110.2
GPIO48: J3.32 R112.2
GPIO49: J3.34 R114.2
GPIO52: J5.2 J5.4 R119.1 U36.6(A4)
GPIO53: J5.6 R55.2 R120.1 R194.2 TVS12.1(A1) U36.5(A3)
GPIO60_3V3: R127.1 R242.2 U25.12(B1)
GPIO61_3V3: R128.1 R243.2 U25.11(B2)
HP_INSERT_DET: C162.1 J7.6 R35.2 R221.2
HP_L: C159.1 J20.3
HP_R: C161.1 J21.3
HPOUTL: J20.2 U1.G1(LINEOUTP(L))
HPOUTR: J21.2 U1.G2(LINEOUTN)
HSY0: J3.51 R51.2 R53.1
I2C0_SCL_1V8: J3.38 J16.1 R234.2 U25.3(A1)
I2C0_SDA_1V8: J3.40 J16.2 R235.2 U25.4(A2)
I2C1_SCL: J3.43 R96.2 R240.2
I2C1_SDA: J3.45 R98.2 R241.2
I2C3_SCL: J3.41 R104.2 R239.2
I2C3_SDA: J3.39 R106.2 R238.2
I2C4_SCL: J4.8 R7.1 R77.1 R236.2
I2C4_SDA: J4.9 R74.1 R79.1 R237.2
JTAG_RST: J12.7 R206.2 U1.V14(GPIO6)
JTAG_TCK: J12.3 R197.2 U1.W15(GPIO2)
JTAG_TDI: J12.5 R199.2 U1.V15(GPIO3)
JTAG_TDO: J12.4 R198.2 U1.Y15(GPIO4)
JTAG_TMS: J12.6 R200.2 U1.U14(GPIO5)
LCD_EN: J4.29 R208.1
LCD_RST: J4.28 R184.1
LDOFB: R281.2 R282.2 U35.15(NC3)
LDOIN: R302.2 U35.18(NC5)
LDOO: C349.1 C350.1 R281.1 R283.1 U35.16(NC4)
MICBIAS: C152.1 C153.1 FB1.1 R31.1 TVS13.1(A1) U1.E3(MIC_BIAS)
MICNL: C154.1 U1.E2(MICIN1N)
MICNR: C156.1 U1.F2(CODEC_MICNR)
MICPL: C157.1 U1.E1(MICIN1P(L))
MICPR: C238.1 U1.F1(CODEC_MICPR)
MIPI_0V8: C85.1 C86.1 C87.1 C357.1 C358.1 R310.2 TP14.1(TP) U1.N6(AVDD0P8_MIPI#N6) U1.R8(AVDD0P8_MIPI#R8)
MIPI_1V8: C88.1 C89.1 C90.1 C345.1 C346.1 R223.2 R311.2 TP12.1(TP) U1.N7(AVDD1P8_MIPI#N7) U1.R9(AVDD1P8_MIPI#R9)
MIPI_RX0_CLK_N: J3.1 U1.Y2(MIPI_RX0_CLK_N)
MIPI_RX0_CLK_P: J3.3 U1.W2(MIPI_RX0_CLK_P)
MIPI_RX0_D0_N: J3.4 U1.W3(MIPI_RX0_D0_N)
MIPI_RX0_D0_P: J3.2 U1.Y3(MIPI_RX0_D0_P)
MIPI_RX0_D1_N: J3.9 U1.V1(MIPI_RX0_D1_N)
MIPI_RX0_D1_P: J3.7 U1.V2(MIPI_RX0_D1_P)
MIPI_RX1_CLK_N: J3.14 U1.W5(MIPI_RX1_CLK_N)
MIPI_RX1_CLK_P: J3.16 U1.Y5(MIPI_RX1_CLK_P)
MIPI_RX1_D2_N: J3.10 U1.Y4(MIPI_RX1_D2_N)
MIPI_RX1_D2_P: J3.8 U1.W4(MIPI_RX1_D2_P)
MIPI_RX1_D3_N: J3.20 U1.W6(MIPI_RX1_D3_N)
MIPI_RX1_D3_P: J3.22 U1.Y6(MIPI_RX1_D3_P)
MIPI_RX2_CLK_N: J3.25 U1.R2(MIPI_RX2_CLK_N)
MIPI_RX2_CLK_P: J3.27 U1.R1(MIPI_RX2_CLK_P)
MIPI_RX2_D4_N: J3.21 U1.T1(MIPI_RX2_D4_N)
MIPI_RX2_D4_P: J3.19 U1.T2(MIPI_RX2_D4_P)
MIPI_RX2_D5_N: J3.13 U1.U2(MIPI_RX2_D5_N)
MIPI_RX2_D5_P: J3.15 U1.U1(MIPI_RX2_D5_P)
MIPI_TX0_CLK_N: J4.19 U1.W9(MIPI_TX0_CLK_N)
MIPI_TX0_CLK_P: J4.20 U1.Y9(MIPI_TX0_CLK_P)
MIPI_TX0_D0_N: J4.22 U1.Y10(MIPI_TX0_D0_N)
MIPI_TX0_D0_P: J4.23 U1.W10(MIPI_TX0_D0_P)
MIPI_TX0_D1_N: J4.16 U1.W11(MIPI_TX0_D1_N)
MIPI_TX0_D1_P: J4.17 U1.Y11(MIPI_TX0_D1_P)
MIPI_TX1_D2_N: J4.13 U1.Y8(MIPI_TX1_D2_N)
MIPI_TX1_D2_P: J4.14 U1.W8(MIPI_TX1_D2_P)
MIPI_TX1_D3_N: J4.25 U1.W7(MIPI_TX1_D3_N)
MIPI_TX1_D3_P: J4.26 U1.Y7(MIPI_TX1_D3_P)
MMC1_CLK: R122.1 R188.2 U4.5(CLK) U22.3(I/O_2)
MMC1_CMD: R121.1 R162.2 U4.3(CMD) U22.2(I/O_1)
MMC1_D0: R123.1 R189.2 U4.7(DAT0) U23.2(I/O_1)
MMC1_D1: R124.1 R190.2 U4.8(DAT1) U23.3(I/O_2)
MMC1_D2: R125.1 R191.2 U4.1(DAT2) U24.2(I/O_1)
MMC1_D3: R126.1 R147.2 R193.2 U4.2(CD/DAT3) U24.3(I/O_2)
MUTE: R130.2 TP25.1(TP) U16.6(MUTE)
NC_NC: J12.8 R207.2
OSPI_CLK: J9.14 U1.K1(GPIO15)
OSPI_CS: J9.6 U1.J5(GPIO14)
OSPI_D0: J9.13 U1.K2(GPIO16)
OSPI_D1: J9.7 U1.K4(GPIO17)
OSPI_D2: J9.9 U1.K5(GPIO18)
OSPI_D3: J9.3 U1.L1(GPIO19)
OSPI_D4: J9.12 U1.L2(GPIO20)
OSPI_D5: J9.5 U1.L3(GPIO21)
OSPI_D6: J9.10 U1.L4(GPIO22)
OSPI_D7: J9.4 U1.L5(GPIO23)
OSPI_DQS: J9.11 U1.L6(GPIO24)
OTP_IO59: J22.2 U34.3(A1)
OUT: C238.2 C314.1 TVS14.1(A1) U29.4(OUT)
OUTL+: R82.1 U16.2(OUTL+)
OUTL-: R84.1 U16.5(OUTL-)
OUTR+: R86.1 U16.14(OUTR+)
OUTR-: R90.1 U16.11(OUTR-)
PW_EN: C268.1 J1.14 J1.16
PWIN_FLASH: C27.1 J9.8 U1.K7(VDDIO3P3_1)
RESET_N_A_B: R64.2 R68.2 U1.J16(DDR_RESET_N)
RTC_1V8: C5.1 C6.1 C343.1 C344.1 FB19.2 J1.4 J1.8 J1.10 R62.2 R262.2 TP13.1(TP) U1.F14(AVDD1P8_LDO) U1.F15(AVDD1P8_RTC)
RTC_CLK_IN: R6.2 U1.B12(CLK32K768_XIN)
RTC_CLK_OUT: R5.1 U1.A12(CLK32K768_XOUT)
RTC_INT0: R1.1 TVS1.1(A1) U1.C10(INT0)
RTC_INT1: R2.1 TVS2.1(A1) U1.B10(INT1)
RTC_INT2: R3.1 TVS6.1(A1) U1.A10(INT2)
RTC_INT3: R4.1 TVS7.1(A1) U1.A11(INT3)
RTC_INT4: R12.1 TVS8.1(A1) U1.C12(INT4)
RTC_INT5: R15.1 TVS9.1(A1) U1.D12(INT5)
RTC_OUT0: R16.1 R62.1 TVS10.1(A1) U1.B11(OUT0)
RTC_OUT1: R22.1 U1.C11(OUT1)
SDL: R80.2 TP26.1(TP) U16.7(SDL)
SDR: R132.2 TP27.1(TP) U16.8(SDR)
SP_L: C309.1 J20.1
SP_R: C311.1 J21.1
SYS_CLK_IN: R10.2 U1.B8(CLK24M_XIN)
SYS_CLK_OUT: R8.2 U1.A8(CLK24M_XOUT)
SYS_ON_OFF: C1.1 J1.2 K1.1
SYS_RST: C13.2 K2.2 R22.2 R223.1 TVS3.1(A1) U1.B9(RSTN)
SYS_SW: R17.1 TVS11.1(A1)
TEST_EN: R129.2 R252.2 U1.A9(TEST_EN)
TOUCH_INT: J4.10 R182.1
TOUCH_RST: J4.11 R183.1
U_3V3: C369.2 R285.2 R287.1 U37.1(OUT)
U_5V: C370.1 J6.A4(VBUS0) J6.A9(VBUS1) J6.B4(VBUS3) J6.B9(VBUS2) U37.4(EN) U37.6(IN)
UART0_RXD: R54.2 R94.2 U25.6(A4)
UART0_RXD_3V3: U25.9(B4) U26.16(ADBUS0)
UART0_TXD: R53.2 R92.2 U25.5(A3)
UART0_TXD_3V3: U25.10(B3) U26.17(ADBUS1)
UART3_CTS_FT: U26.40(BDBUS2) U36.10(B3)
UART3_RTS_FT: U26.41(BDBUS3) U36.9(B4)
UART3_RXD: R117.1 R141.2 U36.3(A1)
UART3_RXD_FT: U26.38(BDBUS0) U36.12(B1)
UART3_TXD: R115.1 R144.2 U36.4(A2)
UART3_TXD_FT: U26.39(BDBUS1) U36.11(B2)
USB0_DN: J11.A7(DN1) J11.B7(DN2) U1.B2(USB0_DN) U32.3(I/O_2)
USB0_DP: J11.A6(DP1) J11.B6(DP2) U1.A2(USB0_DP) U32.2(I/O_1)
USB0_ID: J11.A5(CC1) J11.B5(CC2) U1.D3(USB0_ID) U33.3(I/O_2)
USB0_OTG_EN: J5.1 R41.1 U3.4(EN)
USB0_OTG_VBUS: C17.1 J11.A4(VBUS0) J11.A9(VBUS1) J11.B4(VBUS3) J11.B9(VBUS2) U3.1(OUT)
USB0_VBUS: R39.1 U1.C3(USB0_VBUS)
USB1_DN: J13.A7(DN1) J13.B7(DN2) U1.A4(USB1_DN) U31.3(I/O_2)
USB1_DP: J13.A6(DP1) J13.B6(DP2) U1.B4(USB1_DP) U31.2(I/O_1)
USB1_ID: J13.A5(CC1) J13.B5(CC2) U1.B3(USB1_ID) U33.2(I/O_1)
USB1_OTG_EN: J5.3 R46.1 U6.4(EN)
USB1_OTG_VBUS: C21.1 J13.A4(VBUS0) J13.A9(VBUS1) J13.B4(VBUS3) J13.B9(VBUS2) U6.1(OUT)
USB1_VBUS: R43.1 U1.A3(USB1_VBUS)
VCM: C149.1 C150.1 U1.F3(CODEC_VCM)
VSY0: J3.53 R52.2 R54.1
VTEST: U1.D8(ANA_TS_VTEST) V-TS.1
N20962780: C3.1 R5.2 Y1.1
N20962782: C4.1 R6.1 Y1.2
N20963869: R13.1 SW1.3(B1)
N20963881: R14.1 SW1.4(B2)
N20968799: R61.1 U1.K19(DDR_ZN)
N20974230: R42.1 U1.D4(USB0_TXRTUNE)
N20974244: R44.1 U1.C4(USB1_TXRTUNE)
N20974837: R40.2 U3.3(ISET)
N20975021: R45.2 U6.3(ISET)
N20990724: C11.1 R10.1 Y3.3(IN)
N20990759: C8.1 R8.1 Y3.1(OUT)
N21006529: R65.2 U1.U6(MIPI_ATB)
N21013358: R77.2 U1.W14(GPIO7)
N21013362: R79.2 U1.U12(GPIO8)
N21013366: R81.2 U1.T13(GPIO9)
N21013370: R83.2 U1.U13(GPIO10)
N21013374: R85.2 U1.Y14(GPIO11)
N21013378: R87.2 U1.V13(GPIO12)
N21013382: R89.2 U1.T12(GPIO13)
N21014154: R116.1 U1.T14(GPIO62)
N21014156: R118.1 U1.U15(GPIO63)
N21014379: R92.1 U1.J4(GPIO38)
N21014381: R94.1 U1.J3(GPIO39)
N21014383: R96.1 U1.J2(GPIO40)
N21014385: R98.1 U1.J1(GPIO41)
N21014387: R100.1 U1.H1(GPIO42)
N21014389: R102.1 U1.J6(GPIO43)
N21014391: R104.1 U1.H2(GPIO44)
N21014393: R106.1 U1.H3(GPIO45)
N21014395: R108.1 U1.H4(GPIO46)
N21014397: R110.1 U1.H5(GPIO47)
N21014399: R112.1 U1.G4(GPIO48)
N21014401: R114.1 U1.G5(GPIO49)
N21015109: R115.2 U1.M5(GPIO50)
N21015111: R117.2 U1.M4(GPIO51)
N21015121: R119.2 U1.M3(GPIO52)
N21015123: R120.2 U1.N4(GPIO53)
N21015125: R121.2 U1.M2(GPIO54)
N21015127: R122.2 U1.N2(GPIO55)
N21015129: R123.2 U1.P3(GPIO56)
N21015131: R124.2 U1.N1(GPIO57)
N21015133: R125.2 U1.P1(GPIO58)
N21015135: R126.2 U1.P2(GPIO59)
N21015137: R127.2 U1.P5(GPIO60)
N21015139: R128.2 U1.P4(GPIO61)
N21015638: R91.2 U1.U11(GPIO26)
N21015640: R93.2 U1.W13(GPIO27)
N21015650: R95.2 U1.V12(GPIO28)
N21015652: R97.2 U1.V11(GPIO29)
N21015654: R99.2 U1.V10(GPIO30)
N21015656: R101.2 U1.V9(GPIO31)
N21015658: R103.2 U1.U10(GPIO32)
N21015660: R105.2 U1.T11(GPIO33)
N21015662: R107.2 U1.U9(GPIO34)
N21015664: R109.2 U1.W12(GPIO35)
N21015666: R111.2 U1.T10(GPIO36)
N21015668: R113.2 U1.Y12(GPIO37)
N21034668: C84.1 FB4.1 U1.E9(AVDD3P3_USB)
N21049023: C157.2 J7.1 R31.2
N21049035: C159.2 J7.4
N21049037: C161.2 J7.3
N21049039: J7.8 R33.2
N21049041: J7.7 R34.2
N21049043: C160.2 R34.1
N21049045: C158.2 R33.1
N21090577: C205.1 FB5.1 U1.F9(AVDD1P8_USB)
N21140101: K1.2 R262.1
N21140162: J1.1 R1.2
N21140164: J1.3 R2.2
N21140180: J1.5 R3.2
N21140182: J1.7 R4.2
N21185456: C225.1 C226.1 FB7.2 U26.4(VPHY)
N21185461: C223.1 C224.1 FB8.2 U26.9(VPLL)
N21191941: R201.2 U26.14(RESET#)
N21191953: R202.2 U26.6(REF)
N21192465: R203.2 U26.63(EECS)
N21192467: R204.2 U26.62(EECLK)
N21192469: R205.2 U26.61(EEDATA)
N21250278: R209.2 U25.8(OE)
N21252465: R25.2 U1.C2(ADC_0)
N21252472: R26.2 U1.D2(ADC_1)
N21252475: R27.2 U1.B1(ADC_2)
N21252478: R28.2 U1.G3(ADC_3)
N21252481: R29.2 U1.C1(ADC_4)
N21252484: R30.2 U1.D1(ADC_5)
N21259407: J1.11 R15.2
N21259420: J1.9 R12.2
N21259441: J1.13 R16.2
N21259446: J1.15 R17.2
N21326640: R245.1 U22.4(VCC)
N21346225: GPIO25.1 U1.M1(GPIO25)
N21377535: R47.2 U30.H5(DS)
N21379070: C24.1 U30.C2(VDDI)
N21433380: R50.2 U30.M6(CLK)
N21453086: R55.1 U4.9(DET)
N21464356: J5.8 R141.1
N21464369: J5.10 R144.1
N21465198: R56.2 U1.U7(MIPI_REXT)
N21620702: R64.1 U5.T11(RESET_N)
N21620763: R66.1 U5.A5(ZQ0)
N21620853: R63.1 R72.1 U5.G2(ODT_CA_A)
N21621296: R68.1 U7.T11(RESET_N)
N21621349: R69.1 U7.A5(ZQ0)
N21621402: R67.1 R73.1 U7.G2(ODT_CA_A)
N21701166: C10.1 J18.1 R82.2
N21701169: C305.1 J18.2 R84.2
N21732896: C306.1 J19.1 R86.2
N21732906: C307.1 J19.2 R90.2
N21734873: C309.2 U16.20(INL+)
N21734889: C310.2 U16.19(INL-)
N21735099: C311.2 U16.16(INR+)
N21735109: C312.2 U16.17(INR-)
N21746916: C155.1 FB1.2 U29.1(VDD)
N21763238: Q2.1(GATE) R76.2 R137.2
N21763240: Q2.3(DRAIN) R23.1 R78.1
N21763433: Q1.1(GATE) R78.2
N21776900: R146.2 U34.8(OE)
N21777075: R147.1 U34.12(B1)
N21777236: GPIO1.1 U34.11(B2)
N21777269: J22.1 U34.4(A2)
N21792244: C333.1 R265.1 U35.10(EN1)
N21792661: C334.1 R272.1 U35.9(EN2)
N21792699: C335.1 R273.1 U35.22(EN3)
N21792731: C336.1 R274.1 U35.21(EN4)
N21793143: R277.2 U35.3(NC1)
N21793155: R278.2 U35.6(NC2)
N21799819: R279.1 R280.1 U35.13(GND1)
N21806853: R284.1 U36.8(OE)
N21806875: R285.1 R286.1 U37.2(FB)
N21819738: LED1.1(CATHODE) R19.2
N21842446: C382.1 R294.1 R296.1 U38.1(FB)
N21842448: C377.2 C378.1 C380.1 C382.2 FB34.1 L4.2 R294.2
N21842466: R293.2 U38.2(PG)
N21842648: L4.1 U38.6(LX)
N21859306: K4.2 Q5.1(GATE)
N21859320: K4.1 R303.2
N21859857: C128.2 R177.1 R306.1 U9.1(OUT)
N21859915: C129.1 R143.2 U9.4(EN)
N21859948: R177.2 R178.1 U9.2(FB)
N21888350: L5.1 U35.7(SW2)
N21888386: C320.2 R266.2 R267.1 U35.5(FB2)
N21888844: L11.1 U35.12(SW1)
N21888866: C323.2 R268.2 R269.1 U35.14(FB1)
N21889896: C329.1 C330.1 C331.1 C332.1 FB38.1 L12.2 R270.1 R308.1
N21889964: C332.2 R270.2 R271.1 U35.2(FB3)
N21890180: L12.1 U35.24(SW3)
N21891752: L7.1 U35.19(SW4)
N21891772: C328.2 R275.2 R276.2 U35.17(FB4)
N21913022: C402.1 R304.2 U39.3(EN)
N21913184: C404.2 R305.1 U39.5(VOUT)

Pads without a net: ID1 1; ID2 1; ID3 1; ID4 1; ID5 1; ID6 1; J2 A6 A7 A8 B6 B7 B8; J6 A8 B8; J11 A8 B8; J13 A8 B8; R65 1; U1 A20 C20 D19 D20 F18 G17 H18 H19 J17 J19 K20 L17 L18 L20 M17 M20 N18 P18 T19 Y1 Y20; U5 A1 A2 A8 A11 A12 AA1 AA2 AA4 AA9 AA11 AA12 AB1 AB2 AB11 AB12 B1 B12 G11 H3 J5 K5 K8 N5 N8 P2 P4 P5 P8 P9 P11 R2 R3 R4 R9 R10 R11 T2 U2 U4 U9 U11 V2 V3 V4 V9 V10 V11 W3 W10 Y2 Y3 Y4 Y9 Y10 Y11; U7 A1 A2 A8 A11 A12 AA1 AA2 AA4 AA9 AA11 AA12 AB1 AB2 AB11 AB12 B1 B12 G11 H3 J5 K5 K8 N5 N8 P2 P4 P5 P8 P9 P11 R2 R3 R4 R9 R10 R11 T2 U2 U4 U9 U11 V2 V3 V4 V9 V10 V11 W3 W10 Y2 Y3 Y4 Y9 Y10 Y11; U9 5; U16 10; U23 4; U24 4; U26 18 19 21 22 23 24 26 27 28 29 30 32 33 34 36 43 44 45 46 48 52 53 54 55 57 58 59 60; U30 A1 A2 A7 A8 A9 A10 A11 A12 A13 A14 B1 B7 B8 B9 B10 B11 B12 B13 B14 C1 C3 C5 C7 C8 C9 C10 C11 C12 C13 C14 D1 D2 D3 D4 D12 D13 D14 E1 E2 E3 E5 E8 E9 E10 E12 E13 E14 F1 F2 F3 F10 F12 F13 F14 G1 G2 G3 G10 G12 G13 G14 H1 H2 H3 H12 H13 H14 J1 J2 J3 J12 J13 J14 K1 K2 K3 K6 K7 K10 K12 K13 K14 L1 L2 L3 L12 L13 L14 M1 M2 M3 M7 M8 M9 M10 M11 M12 M13 M14 N1 N3 N6 N7 N8 N9 N10 N11 N12 N13 N14 P1 P2 P7 P8 P9 P10 P11 P12 P13 P14; U31 4; U32 4; U33 4; U34 5 6 9 10; U37 5; U38 5; U39 4

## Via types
v1: diameter 0.559, hole 0.254, TOP to BOTTOM, 949 vias
v2: diameter 0.356, hole 0.203, TOP to BOTTOM, 616 vias
v3: diameter 0.457, hole 0.203, TOP to BOTTOM, 96 vias

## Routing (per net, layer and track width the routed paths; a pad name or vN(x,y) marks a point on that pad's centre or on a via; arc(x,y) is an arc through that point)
AVDD_1V8: length 17.5
  TOP w0.254: v2(31.82,82.61) U1.F7 U1.F8
  TOP w0.381: 63.37,123.06 v1(64.26,123.06) ; R131.2 v1(57.02,129.03) ; 63.37,121.79 v1(64.26,121.79)
  ART03 w0.508: v1(57.02,129.03) 57.91,129.03 63.88,123.06 v1(64.26,123.06)
  BOTTOM w0.254: C14.1 32.26,83.04 v2(31.82,82.61)
  BOTTOM w0.305: 41.78,82.17 41.78,83.06 v1(40.89,83.06) ; 76.2,120.65 R35.1
  vias: v1(44.7,45.47) v1(45.85,46.48) v1(45.85,45.59) v1(54.99,82.04) v1(54.99,80.77)
AVDD_PLL_0V8: length 1.4
  TOP w0.254: U1.G11 v2(31.17,79.36)
  BOTTOM w0.254: v2(31.17,79.36) 31.67,78.87 C32.1
  vias: v1(51.82,70.36) v1(52.83,70.36) v1(52.83,69.34)
GND: length 393.9
  TOP w0.076: v2(45.97,115.79) 45.73,116.03 44.91,116.03 U30.N2 44.91,115.53 45.72,115.53 v2(45.97,115.79)
  TOP w0.203: U30.A6 42.29,109.41 v2(42.29,109.22) ; v1(62.23,99.82) 61.92,100.13 U34.7 ; v1(52.7,107.31) 53.01,107.62 U36.7 ; v2(42.16,116.71) 42.23,116.71 U30.P6 U30.N5 U30.P4 v2(43.66,116.7) ; U30.K8 41.78,114.16 v2(41.78,113.79) 41.78,113.67 41.4,113.28 U30.H10 ; v2(43.08,111.26) 43.18,111.26 U30.C4 ; U25.7 67,116.12 v1(66.82,115.94) ; U30.G5 42.42,112.78 v2(42.41,112.77) 42.16,112.52 U30.E7
  TOP w0.254: v2(30.12,45.58) 30.45,45.91 U7.Y1 ; U5.T8 23.5,48.51 v2(23.83,48.18) ; v2(24.63,48.83) 24.95,48.51 U5.T10 ; U7.J1 30.45,53.06 v2(30.12,53.38) ; U7.A3 31.8,58.58 v2(31.72,58.58) ; v2(38.13,52.08) 38.2,52.08 U7.K11 ; U1.T8 v2(24.68,81.96) U1.U8 ; v2(27.03,45.58) 26.7,45.91 U5.Y12 ; v2(30.12,57.28) 30.45,56.96 U7.C1 ; v2(31.72,44.28) 32.05,44.61 U7.AB3 ; U7.G3 32.2,54.36 v2(32.52,54.03) ; U1.Y19 v2(22.73,74.16) U1.W20 ; U5.K4 20.55,52.08 v2(20.62,52.08) ; U1.P7 v2(26.63,81.96) ; v2(26.63,81.96) U1.P8 ; v2(26.63,81.96) U1.N8 ; v2(30.52,76.11) U1.H16 U1.J15 ; v2(39.73,55.33) 39.4,55.66 U7.E12 ; U7.D2 31.25,56.31 v2(30.92,56.63) ; U16.4 58.92,121.33 ; U1.P10 v2(26.63,80.66) ; v2(30.92,46.23) 31.25,46.56 U7.W2 ; U7.J3 32.05,53.06 v2(31.72,53.38) ; U5.C1 17.75,56.96 v2(17.42,57.28) ; U7.D11 38.6,56.31 v2(38.93,56.63) ; U1.D11 v2(33.12,80.01) U1.D10 32.95,80.48 32.95,80.84 U1.D9 ; v2(36.53,52.08) 36.6,52.08 U7.K9 ; U5.W4 20.15,46.56 v2(19.82,46.23) ; U7.P3 32.45,49.48 v2(32.52,49.48) ; v2(26.63,80.01) 26.95,80.33 U1.N10 ; U1.R12 v2(25.33,78.71) ; U1.G15 v2(31.17,76.76) U1.G16 ; U1.G15 v2(31.17,77.41) U1.G14 ; U1.G15 U1.H15 ; U1.P14 v2(25.98,77.41) U1.R14 ; v2(18.22,56.63) 18.55,56.31 U5.D2 ; v2(33.32,47.53) 33.65,47.21 U7.V5 ; v2(34.12,44.28) 34.05,44.28 U7.AB5 ; U26.51 57.96,105.01 ; U1.T3 v2(25.33,85.21) U1.R3 ; v2(21.46,78.38) 21.49,78.38 21.49,78.39 U1.Y13 ; U1.U3 v2(24.03,85.21) U1.V3 ; v2(35.18,78.39) U1.A13 U1.B13 ; U26.10 64.25,109.23 ; U1.F6 31.38,83.06 30.97,83.06 U1.G6 v2(30.52,83.26) ; v2(26.23,48.83) 26.55,48.51 U5.T12 ; U7.D4 32.85,56.31 v2(32.52,56.63) ; U1.K16 v2(29.22,76.11) ; v2(34.12,55.98) 34.05,55.98 U7.E5 ; U1.K8 v2(29.22,81.31) ; U1.P6 U1.R6 v2(25.33,83.26) ; v2(27.03,46.88) 26.7,47.21 U5.V12 ; U5.T1 17.75,48.51 v2(17.42,48.18) ; v2(31.17,82.61) U1.G7 U1.G8 ; v2(27.03,49.48) 26.7,49.81 U5.P12 ; v2(35.73,57.28) 35.8,57.28 U7.C8 ; U5.W11 26.15,46.23 v2(26.23,46.23) ; U7.AB8 36.2,44.61 v2(36.53,44.28) ; U5.D11 25.9,56.31 v2(26.23,56.63) ; v2(32.52,46.23) 32.85,46.56 U7.W4 ; v2(18.22,50.13) 18.55,50.46 U5.N2 ; U7.E8 36.2,55.66 v2(36.53,55.33) ; v2(30.12,49.48) 30.45,49.81 U7.P1 ; v2(21.42,55.33) 21.1,55.66 U5.E5 ; U1.N3 v2(27.28,84.56) ; U1.N5 v2(26.63,83.91) ; v2(33.32,50.13) 33.25,50.13 U7.N4 ; v2(20.62,55.98) 20.3,56.31 U5.D4 ; U5.Y8 23.75,45.58 v2(23.83,45.58) ; U7.A10 38.05,58.58 v2(38.13,58.58) ; v2(23.83,54.69) 23.5,54.36 U5.G8 ; v2(19.02,52.73) 19.35,53.06 U5.J3 ; v2(23.83,57.28) 23.5,56.96 U5.C8 ; v2(38.93,46.23) 38.85,46.23 U7.W11 ; U1.F16 v2(31.82,76.11) U1.E16 ; U1.G13 v2(30.53,78.06) ; v2(26.23,54.68) 26.55,54.36 U5.G12 ; v2(23.83,46.88) 23.5,47.21 U5.V8 ; U5.C12 26.7,56.96 v2(27.03,57.28) ; v2(24.63,58.58) 24.7,58.58 U5.A10 ; U1.M16 v2(27.28,76.11) ; U1.N15 v2(26.63,76.76) U1.N16 ; v2(23.83,50.13) 23.9,50.13 U5.N9 ; U7.C5 34.05,57.28 v2(34.12,57.28) ; v2(23.83,52.08) 23.9,52.08 U5.K9 ; v2(36.53,50.13) 36.6,50.13 U7.N9 ; v2(33.32,45.58) 33.65,45.91 U7.Y5 ; U5.K11 25.9,52.41 v2(26.23,52.73) ; U1.B20 U1.A19 v2(35.08,74.16) ; v2(37.33,54.03) 37.4,54.03 U7.G10 ; U1.E8 v2(32.47,81.96) 32.15,82.28 U1.E7 v2(32.47,82.61) 32.15,82.93 U1.E6 ; U5.W2 18.55,46.56 v2(18.22,46.23) ; v2(39.73,46.88) 39.4,47.21 U7.V12 ; U1.F4 31.5,84.23 v2(31.82,83.91) U1.E4 ; v2(20.62,54.68) 20.95,54.36 U5.G5 ; U1.R16 v2(25.33,76.76) U1.T15 ; v2(17.42,52.73) 17.75,53.06 U5.J1 ; U7.Y8 36.45,45.58 v2(36.53,45.58) ; U1.E12 32.15,79.03 v2(32.47,78.71) U1.D13 ; U7.T8 36.2,48.51 v2(36.53,48.18) ; U1.V4 23.7,84.23 v2(23.38,83.91) U1.V5 ; U7.J12 39.4,53.06 v2(39.73,52.73) ; U26.25 60.46,111.91 ; v2(30.92,54.68) 30.6,54.36 U7.G1 ; U5.T3 19.35,48.51 v2(19.02,48.18) ; v2(20.62,50.13) 20.55,50.13 U5.N4 ; v2(31.72,48.18) 32.05,48.51 U7.T3 ; U5.AB3 19.35,44.61 v2(19.02,44.28) ; U7.P12 39.4,49.81 v2(39.73,49.48) ; v2(20.62,45.58) 20.95,45.91 U5.Y5 ; U1.W1 v2(22.73,86.51) ; U5.J12 26.55,53.06 v2(26.23,53.38) ; U7.C12 39.4,56.96 v2(39.73,57.28) ; U1.J7 v2(29.87,82.61) U1.H7 ; v2(17.42,45.58) 17.75,45.91 U5.Y1 ; v2(37.33,44.93) 37.65,44.61 U7.AB10 ; U1.T9 v2(25.33,80.66) U1.R10 ; v2(38.93,54.68) 39,54.68 U7.G12 ; U1.M10 v2(27.28,80.66) ; v2(38.13,52.73) 37.8,53.06 U7.J10 ; v2(19.82,58.71) 19.42,58.31 U5.A3 ; v2(23.03,55.98) 23.1,55.98 U5.E8 ; U1.A16 v2(35.65,76.44) ; U1.E19 v2(31.83,74.16) ; U5.C5 21.1,56.96 v2(21.42,56.63) ; U26.47 v1(55.13,105.23) ; U1.C13 v2(33.12,78.06) ; U1.W16 v2(23.38,76.76) ; v2(20.62,47.53) 20.95,47.21 U5.V5 ; v2(43.68,113.65) 43.55,113.78 U30.J5 ; U5.G10 25.1,54.36 v2(25.43,54.03) ; v2(26.23,55.98) 26.3,55.98 U5.E12 ; U7.K2 31.65,52.73 v2(31.72,52.73) ; v2(35.73,54.68) 35.8,54.68 U7.G8 ; v2(38.93,50.13) 38.6,50.46 U7.N11 ; v2(30.12,48.18) 30.45,48.51 U7.T1 ; v2(30.12,46.88) 30.45,47.21 U7.V1 ; v2(38.93,48.83) 39.25,48.51 U7.T12 ; v2(19.02,52.08) 18.95,52.08 U5.K2 ; U1.F10 v2(31.17,80.66) ; U26.11 64.25,109.73 ; U1.H20 v2(29.87,73.51) ; U1.P12 v2(26.63,78.71) U1.N12 ; U1.P20 v2(26.63,73.51) ; U26.35 57.11,111.23 ; U1.V6 23.7,82.93 v2(23.38,82.61) U1.V7 ; v2(17.42,55.33) 17.75,55.66 U5.E1 ; U1.K3 v2(29.22,85.21) ; v2(30.92,50.13) 31.25,50.46 U7.N2 ; U1.K14 v2(29.22,78.06) ; U1.V8 v2(23.38,81.96) ; U5.G3 19.35,54.36 v2(19.02,54.68) ; v2(33.32,48.18) 33.65,48.51 U7.T5 ; v2(20.62,48.18) 20.95,48.51 U5.T5 ; U1.L8 v2(27.93,81.96) U1.M8 ; U5.P10 25.1,49.81 v2(25.43,49.48) ; U1.L19 v2(28.58,74.81) U1.K18 ; v2(33.12,76.76) U1.D15 U1.E15 ; U7.K4 33,52.41 v2(33.32,52.08) ; U1.H13 v2(29.87,78.06) U1.J13 ; v2(34.12,54.68) 34.05,54.68 U7.G5 ; v2(17.35,54.68) 17.67,54.36 U5.G1 ; v2(17.42,46.88) 17.75,47.21 U5.V1 ; v2(24.63,52.73) 24.7,52.73 U5.J10 ; U16.12 58.92,123.53 ; v2(38.13,49.48) 37.8,49.81 U7.P10 ; v2(37.33,48.83) 37.65,48.51 U7.T10 ; U1.E13 v2(31.82,78.06) U1.E14 ; v1(66.3,104.41) 65.99,104.73 U26.1 ; U7.Y12 39.4,45.91 v2(39.73,45.58) ; U26.13 64.25,110.73 ; U7.W9 37,46.56 v2(37.33,46.23) ; v2(36.53,55.98) 36.85,56.31 U7.D9 ; U26.15 64.19,111.73 ; U7.E1 30.45,55.66 v2(30.12,55.98) ; U1.M6 v2(27.93,82.61) U1.L7 ; U1.F11 v2(31.82,80.01) ; U5.W9 24.3,46.56 v2(24.63,46.23) ; v2(17.42,49.48) 17.75,49.81 U5.P1 ; U1.K6 v2(29.22,82.61) ; U5.AB8 23.5,44.61 v2(23.83,44.28) ; U26.5 64.25,106.73 ; U35.4 53.97,32.63 ; v2(25.98,76.76) U1.P15 ; v2(26.23,50.13) 25.9,50.46 U5.N11 ; U5.D9 24.3,56.31 v2(24.63,56.63) ; U16.18 57.27,122.56 ; U1.M15 v2(27.93,76.76) U1.L15 ; v2(19.02,49.48) 19.35,49.81 U5.P3 ; U1.J11 v2(29.87,80.01) U1.H11 ; v2(36.53,46.88) 36.2,47.21 U7.V8 ; U1.R7 v2(25.33,82.61) U1.T7 ; v2(29.22,79.36) U1.K12 28.81,79.12 28.34,79.12 U1.L12 ; U1.L10 v2(27.93,80.66) ; U1.U19 v2(24.68,74.16) ; v2(24.63,44.93) 24.95,44.61 U5.AB10 ; v2(20.62,44.28) 20.95,44.61 U5.AB5 ; U1.M12 v2(27.28,78.71) ; U1.K10 v2(28.58,80.66)
  TOP w0.305: J3.6 v1(33.75,132.59) ; v1(65.3,119.25) 65.3,119.75 C207.2 ; U38.8 59.7,77.24 ; TVS10.2 v1(20.32,7.87) ; J4.2 6.73,89.41 v1(6.48,89.15) 6.72,88.91 J4.1 ; J3.12 v1(35.25,132.59) ; J3.55 v3(46.26,128.93) ; J4.24 v3(6.91,100.41) ; TVS8.2 v1(25.4,7.87) ; v1(45.91,132.59) 45.76,132.74 J3.54 ; J4.27 v3(6.91,101.91) ; TVS7.2 v1(27.94,7.87) ; J4.18 v3(6.91,97.41) ; TVS2.2 v1(32.89,7.87) ; C42.2 43.56,77.72 ; J4.15 v1(6.91,95.91) ; J4.30 v1(6.91,103.41) ; J3.18 v1(36.75,132.59) ; TVS11.2 v1(16.51,7.87) ; J3.5 v1(33.75,128.75) ; C204.2 69.73,101.74 ; TVS6.2 v1(30.48,7.87) ; J3.11 v1(35.25,128.75) ; C394.2 v1(56.26,81.15) ; J3.23 v1(38.25,128.75) ; C208.1 v1(68.73,119.25) ; J3.17 v1(36.75,128.75) ; v1(6.48,91.91) J4.7 ; J4.21 v3(6.91,98.91) ; J3.29 v1(39.75,128.75) ; J3.28 v1(39.25,132.59) ; J4.12 v1(6.91,94.41) ; J3.33 v1(40.76,128.78) 41.45,128.78 41.76,129.08 J3.37 ; R296.2 v1(56.77,78.61) ; J3.24 v1(38.25,132.59) ; TVS9.2 v1(22.86,7.87) ; TVS1.2 v1(35.18,7.87)
  TOP w0.381: C306.2 v1(60.59,133.47) ; v1(51.05,112.65) 50.16,111.76 50.16,106.68 v1(52.7,104.14) 56.01,100.84 v1(56.01,96.14) ; J7.2 v1(74.4,126.11) ; U31.1 70.22,64.77 v1(71.12,64.77) ; LED1.2 v1(16.76,17.65) ; v1(49.28,85.09) 49.15,85.22 R44.2 R42.2 ; R290.2 v1(59.56,30.1) ; v1(64.03,84.99) U4.6 ; U6.2 v1(68.96,58.29) ; C8.2 50.16,77.98 ; 14.1,10.03 v1(14.1,10.92) ; C11.2 v1(50.29,82.04) ; TVS13.2 v1(66.55,135.64) ; C349.2 v1(47.88,34.04) ; C303.2 v1(59.69,115.82) ; C206.1 6.22,52.7 v1(6.48,52.45) ; R195.2 v1(66.55,109.6) ; U33.1 v1(70.36,77.98) ; C4.2 v1(50.16,76.33) 52.58,76.33 v1(52.7,76.2) 52.83,76.07 v1(52.83,74.04) v1(52.83,72.14) 52.45,71.75 v1(50.42,71.75) 50.16,71.75 C3.2 ; U3.2 v1(68.96,68.45) ; 57.02,89.92 v1(56.26,89.92) ; C350.2 v1(46.61,34.29) ; R278.1 v1(59.56,33.53) ; U32.1 v1(70.41,75) ; TP16.1 v1(14.22,19.68) ; R252.1 48.39,75.69 v1(48.26,75.56) ; C336.2 C335.2 53.21,25.15 v1(52.96,24.89) ; 63.37,120.52 v1(64.26,120.52) ; C129.2 v1(31.24,23.5) ; K2.1 v1(76.83,53.98) ; Q2.2 v1(25.02,37.21) ; C316.1 C315.2 v1(56.9,99.06) ; 21.72,23.5 v1(21.72,22.48) ; C399.2 v1(62.87,23.62) ; J9.2 v1(30.8,119.95) ; R133.2 v1(55.75,129.03) ; v1(54.86,112.9) 52.7,112.9 ; v1(70.74,132.46) C314.2 70.1,133.48 TVS14.2 ; R137.1 v1(29.34,36.58) ; J9.15 30.8,105.35 v1(31.24,105.79) ; v1(52.58,122.05) C310.1 C312.1 ; R134.2 C313.2 v1(57.15,115.82) ; 52.07,38.99 53.21,38.99 v1(53.21,40.13) ; C49.2 48.64,82.17 v1(48.39,81.92) ; R279.2 v1(44.32,35.18) ; 66.04,101.35 66.04,101.87 C201.2 ; C7.2 v1(58.42,115.82) ; C155.2 v1(68.71,132.46) ; TP17.1 v1(15.24,40.26) ; C34.2 43.56,76.96 ; U37.3 61.01,90.54 ; 63.37,124.21 v1(64.26,124.21) ; U9.3 25.92,24.12 ; TP19.1 v1(39.12,18.41) ; C1.2 v1(71.25,24.13) ; C400.2 v1(62.87,25.78) ; C307.2 v1(63.87,133.47) ; 21.72,16.51 v1(20.7,16.51)
  BOTTOM w0.203: 31.88,81.92 31.92,81.96 v2(32.47,81.96)
  BOTTOM w0.254: C85.2 24.41,85.85 24.03,85.47 v2(24.03,85.21) ; v2(32.52,56.63) 32.53,56.64 C293.2 ; v2(37.97,79.12) C78.2 37.85,79.63 C83.2 C82.2 ; C74.2 29.16,76.17 v2(29.22,76.11) ; C14.2 31.24,82.68 v2(31.17,82.61) ; v2(30.52,76.11) 30.53,76.1 C262.2 ; C84.2 37.76,81.53 v2(37.85,81.45) 37.93,81.53 C35.2 C48.2 C45.2 ; C79.2 C27.2 ; C79.2 29.21,90.55 v2(29.59,90.93) ; C79.2 C29.2 ; C56.2 C52.2 30.99,80.85 v2(31.17,80.66) ; C87.2 25.69,84.92 25.61,84.92 v2(25.33,85.21) 25.84,85.72 25.91,85.72 C30.2 C81.2 ; v2(38.13,58.58) 38.09,58.55 C286.2 ; C86.2 24.89,83.69 v2(25.33,83.26) ; v2(17.42,52.08) 17.27,51.93 C263.2 ; v2(42.41,112.77) 42.04,112.39 C258.2 ; C89.2 24.06,81.28 v2(23.38,81.96) 22.94,81.96 R56.1 ; v2(29.87,73.51) 29.97,73.41 C261.1 ; v2(28.58,74.81) 28.57,74.8 C71.2 ; C90.2 C47.2 ; C66.2 C65.2 23.17,76.96 v2(23.38,76.76) ; C25.2 45.81,115.95 v2(45.97,115.79) ; C58.2 C61.2 ; v2(41.02,109.22) 40.89,109.35 C256.2 ; v2(26.63,80.01) 26.75,79.88 C40.2 ; C88.2 v2(20.45,78.38) ; C31.2 v2(21.46,78.38) C80.2 C28.2 ; v2(29.22,78.06) 29.21,78.08 C68.2 ; C257.2 v2(42.16,116.71)
  BOTTOM w0.305: v1(30.8,119.95) 30.8,120.21 C242.1 ; v2(31.83,74.16) 32.01,74.16 32.64,73.53 ; v3(30.99,89.66) C149.2 C156.2 ; v1(43.69,85.09) 43.43,84.84 C51.2 ; C50.2 43.56,83.95 v1(43.69,84.07) ; C200.1 57.54,111.65 v1(57.79,111.4) ; C221.1 57.67,110.38 ; C37.2 39.12,73.81 v2(38.99,73.69) 39.12,73.56 C36.2 ; C150.2 32.26,84.34 v2(31.82,83.91) ; R58.2 v1(30.86,69.85) 30.99,69.98 C72.2 ; C219.1 57.67,107.84 ; v2(43.08,111.26) 43.15,111.26 43.15,111.25 C22.2 C19.2
  BOTTOM w0.381: 61.85,125.86 v1(62.87,125.86) ; C222.1 63.51,105.43 v1(63.63,105.56) ; R45.1 v1(68.96,60.07) ; C20.1 v1(66.42,56.13) C21.2 ; C199.1 63.63,110.51 ; R9.2 v1(75.82,14.48) ; R282.1 46.61,31.24 v1(46.86,30.99) R276.1 ; TVS3.2 v1(77.72,50.29) ; C162.2 v1(77.47,121.16) ; 33.91,86.23 33.91,88.39 ; v1(66.77,61.55) 66.77,61.43 R46.2 ; C160.1 72.66,123.94 v1(72.39,124.21) ; v1(43.69,83.06) C55.2 C151.2 ; C216.1 58.43,105.43 ; TVS12.2 71.39,84.07 v1(70.99,84.07) ; C306.2 v1(60.59,133.47) ; 32.64,73.53 32.38,73.28 C269.2 ; R61.2 26.67,73.47 v2(26.63,73.51) ; C224.2 63.76,109.49 ; 63.76,106.19 C225.2 C226.2 ; R271.2 v1(59.56,32.38) ; R202.1 63.76,107.34 ; R40.1 68.83,70.1 v1(68.96,70.23) ; C220.1 62.61,105.54 ; R41.2 66.29,70.1 v1(66.42,70.23) ; C16.1 v1(66.42,66.17) ; R279.2 v1(44.32,35.18) ; C259.2 v1(36.7,108.71) ; C13.1 v1(75.82,50.8) ; v1(45.72,113.16) 45.47,112.9 C24.2 ; C203.1 62.62,111.27 ; U22.1 64.66,86.87 v1(64.14,86.87) ; R74.2 v1(6.1,81.92) ; v1(71.5,54.61) TVS4.2 TVS5.2 ; C307.2 v1(63.87,133.47) ; R7.2 v1(6.6,86.11) ; v1(57.79,105.56) 57.54,105.3 C217.1 C202.1 ; C44.2 C43.2 43.31,80.64 v1(43.69,80.26) ; C223.2 v1(63.63,108.48) ; R278.1 v1(59.56,33.53) ; 33.91,88.39 34.8,88.39 v3(34.92,88.27) ; 33.91,88.39 v3(33.91,89.03) ; U23.1 v1(64.01,83.69) ; C18.2 41.15,116.33 ; C158.1 v1(68.71,127.13) ; C17.2 v1(68.96,66.17) ; C218.1 60.46,105.43 ; R14.2 v1(69.34,44.32) R13.2 ; C260.2 v1(31.24,105.79) ; U24.1 v1(66.17,91.31)
  vias: v1(1.52,126.75) v1(1.52,121.67) v1(1.52,117.6) v1(1.52,109.73) v1(1.52,103.89) v1(4.95,85.34) v1(5.08,107.57) v1(6.35,107.57) v1(6.35,106.3) v1(6.35,105.03) v1(7.37,124.21) v1(7.37,119.38) v1(19.3,20.57) v1(19.3,19.3) v1(20.57,19.3) v1(20.75,66.22) v1(20.75,65.2) v1(23.5,30.1) v1(24.77,30.1) v1(24.77,28.83) v1(24.77,23.24) v1(26.04,30.1) v1(26.04,28.83) v1(26.04,26.42) v1(26.04,24.77) v1(26.04,23.24) v1(27.3,30.1) v1(27.3,28.83) v1(27.3,26.42) v1(27.3,23.24) v1(27.81,16.89) v1(27.81,15.62) v1(29.08,16.89) v1(29.08,15.62) v1(30.35,15.62) v1(31.88,21.34) v1(33.15,21.34) v1(33.15,20.07) v1(34.42,21.34) v1(34.42,20.07) v1(37.59,124.97) v1(39.75,37.21) v1(39.88,32.51) v1(39.88,31.5) v1(39.88,30.48) v1(40.89,32.51) v1(40.89,31.5) v1(40.89,30.48) v1(41.02,37.21) v1(41.78,56.39) v1(41.78,55.12) v1(41.78,53.85) v1(41.78,52.58) v1(41.78,51.31) v1(41.78,50.04) v1(41.78,48.77) v1(41.78,47.5) v1(41.78,46.23) v1(41.78,44.96) v1(41.78,43.69) v1(41.78,39.88) v1(41.91,32.51) v1(41.91,31.5) v1(42.67,20.45) v1(42.67,19.18) v1(42.67,17.91) v1(42.8,55.12) v1(42.8,51.31) v1(42.8,47.5) v1(42.93,32.51) v1(42.93,31.5) v1(43.05,43.69) v1(43.05,39.88) v1(43.69,78.36) v1(43.69,77.22) v1(43.94,20.45) v1(43.94,19.18) v1(43.94,17.91) v1(44.58,83.06) v1(44.68,78.36) v1(44.68,77.22) v1(45.21,20.45) v1(45.21,19.18) v1(45.21,17.91) v1(45.85,6.35) v1(45.85,5.08) v1(45.85,3.81) v1(45.85,2.54) v1(45.97,61.47) v1(46.23,72.52) v1(46.23,71.63) v1(46.48,21.72) v1(46.48,20.45) v1(46.48,19.18) v1(46.48,17.91) v1(46.99,61.47) v1(46.99,60.2) v1(47.12,6.35) v1(47.12,5.08) v1(47.12,3.81) v1(47.12,2.54) v1(47.24,72.52) v1(47.62,21.72) v1(48.26,61.47) v1(48.26,60.2) v1(48.39,3.81) v1(48.39,2.54) v1(49.66,3.81) v1(49.66,2.54) v1(50.42,24.89) v1(50.55,40.13) v1(50.67,23.62) v1(50.67,22.48) v1(50.8,62.74) v1(50.8,61.47) v1(50.8,60.2) v1(50.8,58.93) v1(50.8,57.66) v1(50.8,56.39) v1(50.8,55.12) v1(50.8,53.72) v1(50.8,52.58) v1(50.8,51.31) v1(50.8,50.04) v1(50.8,48.77) v1(50.8,47.5) v1(50.8,46.23) v1(50.8,44.96) v1(50.93,77.22) v1(50.93,6.35) v1(50.93,5.08) v1(50.93,3.81) v1(50.93,2.54) v1(51.31,82.04) v1(51.44,40.13) v1(51.44,24.89) v1(51.82,33.27) v1(51.82,31.5) v1(51.94,64.14) v1(51.94,23.62) v1(51.94,22.48) v1(52.07,47.5) v1(52.07,46.23) v1(52.07,44.96) v1(52.07,43.69) v1(52.07,42.42) v1(52.07,41.27) v1(52.2,6.35) v1(52.2,5.08) v1(52.2,3.81) v1(52.2,2.54) v1(52.32,82.04) v1(52.32,56.39) v1(52.32,55.12) v1(52.45,77.22) v1(52.7,32.38) v1(53.21,23.62) v1(53.21,22.48) v1(53.34,44.96) v1(53.34,41.27) v1(53.47,6.35) v1(53.47,5.08) v1(53.47,3.81) v1(53.47,2.54) v1(53.59,82.04) v1(53.59,33.27) v1(53.59,31.5) v1(53.98,24.89) v1(54.1,79.63) v1(54.1,77.22) v1(54.36,40.13) v1(54.48,23.62) v1(54.48,22.48) v1(54.74,6.35) v1(54.74,5.08) v1(54.74,3.81) v1(54.74,2.54) v1(54.99,124.84) v1(54.99,24.89) v1(55.37,40.13) v1(55.75,20.32) v1(55.88,83.82) v1(55.88,82.93) v1(56.01,119.13) v1(56.01,6.35) v1(56.01,5.08) v1(56.01,3.81) v1(56.01,2.54) v1(56.77,131.44) v1(56.9,20.32) v1(57.15,82.93) v1(57.28,6.35) v1(57.28,5.08) v1(57.28,3.81) v1(57.28,2.54) v1(57.53,61.59) v1(57.53,60.33) v1(57.53,59.05) v1(57.78,123.19) v1(57.78,121.92) v1(57.79,109.75) v1(57.79,108.48) v1(57.79,107.21) v1(58.04,20.32) v1(58.04,19.05) v1(58.17,126.62) v1(58.55,6.35) v1(58.55,5.08) v1(58.55,3.81) v1(58.55,2.54) v1(58.8,61.59) v1(58.8,60.33) v1(58.8,59.05) v1(59.05,123.19) v1(59.05,121.92) v1(59.18,76.83) v1(59.18,20.32) v1(59.18,19.05) v1(59.44,111.4) v1(59.44,109.75) v1(59.44,108.48) v1(59.44,107.21) v1(59.44,105.56) v1(59.82,3.81) v1(59.82,2.54) v1(59.94,88.14) v1(59.94,86.87) v1(60.45,76.83) v1(60.58,131.44) v1(60.58,129.03) v1(60.71,111.4) v1(60.71,109.75) v1(60.71,108.48) v1(60.71,107.21) v1(60.71,105.56) v1(61.09,3.81) v1(61.09,2.54) v1(61.21,126.87) v1(61.21,88.14) v1(61.21,86.87) v1(61.34,92.46) v1(61.34,91.19) v1(61.34,89.92) v1(61.85,76.83) v1(61.85,75.56) v1(61.85,74.3) v1(61.98,111.4) v1(61.98,109.75) v1(61.98,108.48) v1(61.98,107.21) v1(61.98,105.56) v1(62.36,46.35) v1(62.36,45.09) v1(62.36,43.69) v1(62.36,6.35) v1(62.36,5.08) v1(62.36,3.81) v1(62.36,2.54) v1(62.48,88.14) v1(62.48,86.87) v1(62.99,76.83) v1(62.99,75.56) v1(62.99,74.3) v1(62.99,73.03) v1(62.99,71.75) v1(62.99,70.48) v1(63.51,111.4) v1(63.63,109.75) v1(63.63,107.21) v1(63.63,46.35) v1(63.63,45.09) v1(63.63,43.69) v1(63.63,6.35) v1(63.63,5.08) v1(63.63,3.81) v1(63.63,2.54) v1(64.14,131.57) v1(64.14,129.03) v1(64.9,50.16) v1(64.9,48.9) v1(64.9,47.62) v1(64.9,46.35) v1(64.9,45.09) v1(64.9,43.69) v1(64.9,6.35) v1(64.9,5.08) v1(64.9,3.81) v1(64.9,2.54) v1(65.66,96.27) v1(65.79,100.71) v1(65.79,99.44) v1(65.79,98.17) v1(65.91,42.16) v1(66.17,74.38) v1(66.17,71.33) v1(66.17,6.35) v1(66.17,5.08) v1(66.29,79.12) v1(66.77,63.84) v1(66.93,96.27) v1(67.18,42.16) v1(67.69,80.33) v1(67.82,138.68) v1(67.94,98.17) v1(68.45,42.16) v1(69.72,42.16) v1(69.85,100.97) v1(69.85,99.57) v1(69.85,98.17) v1(70.74,138.68) v1(70.99,42.16) v1(71.25,108.33) v1(72.26,42.16) v1(73.66,42.16) v1(73.66,40.89) v1(73.91,86.23) v1(74.62,97.41) v1(74.62,94.87) v1(74.62,81.6) v1(74.93,42.16) v1(74.93,40.89) v1(75.06,88.9) v1(75.06,87.63) v1(75.06,86.23) v1(75.89,97.41) v1(75.89,94.87) v1(75.89,81.6) v1(77.16,97.41) v1(77.16,96.14) v1(77.16,94.87) v1(77.16,81.6) v1(77.16,80.33) v2(18.22,48.83) v2(18.22,47.53) v2(19.02,46.88) v2(19.02,46.23) v2(19.68,75.95) v2(19.82,44.93) v2(21.42,50.13) v2(21.42,44.93) v2(21.42,44.28) v2(22.23,44.28) v2(22.99,72.3) v2(23.03,50.13) v2(24.63,47.53) v2(25.98,80.66) v2(30.92,48.83) v2(30.92,47.53) v2(31.72,46.88) v2(31.72,46.23) v2(32.52,44.93) v2(34.12,53.38) v2(34.12,50.13) v2(34.12,44.93) v2(34.92,44.28) v2(35.73,50.13) v2(35.81,75.44) v2(36.31,78.04) v2(37.33,47.53) v2(38,116.71) v2(38,115.7) v2(38.93,53.38) v2(39.5,116.71) v2(39.73,52.08) v2(40.77,116.71) v3(2.16,99.75) v3(2.16,93.68) v3(2.16,91.4) v3(3.25,98.04) v3(3.25,95.37) v3(3.76,89.69) v3(3.76,87.02) v3(9.86,83.57) v3(11.58,83.57) v3(11.81,86.19) v3(13.59,87.45) v3(13.61,83.57) v3(14.62,84.89) v3(42.42,71.12) v3(42.42,70.1) v3(43.56,70.36) v3(43.56,69.47) v3(45.59,87.64) v3(45.59,86.01)
